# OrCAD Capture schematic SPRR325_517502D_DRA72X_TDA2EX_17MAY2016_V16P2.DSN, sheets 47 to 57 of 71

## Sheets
47 SH58 - ETHERNET PORT0: size B
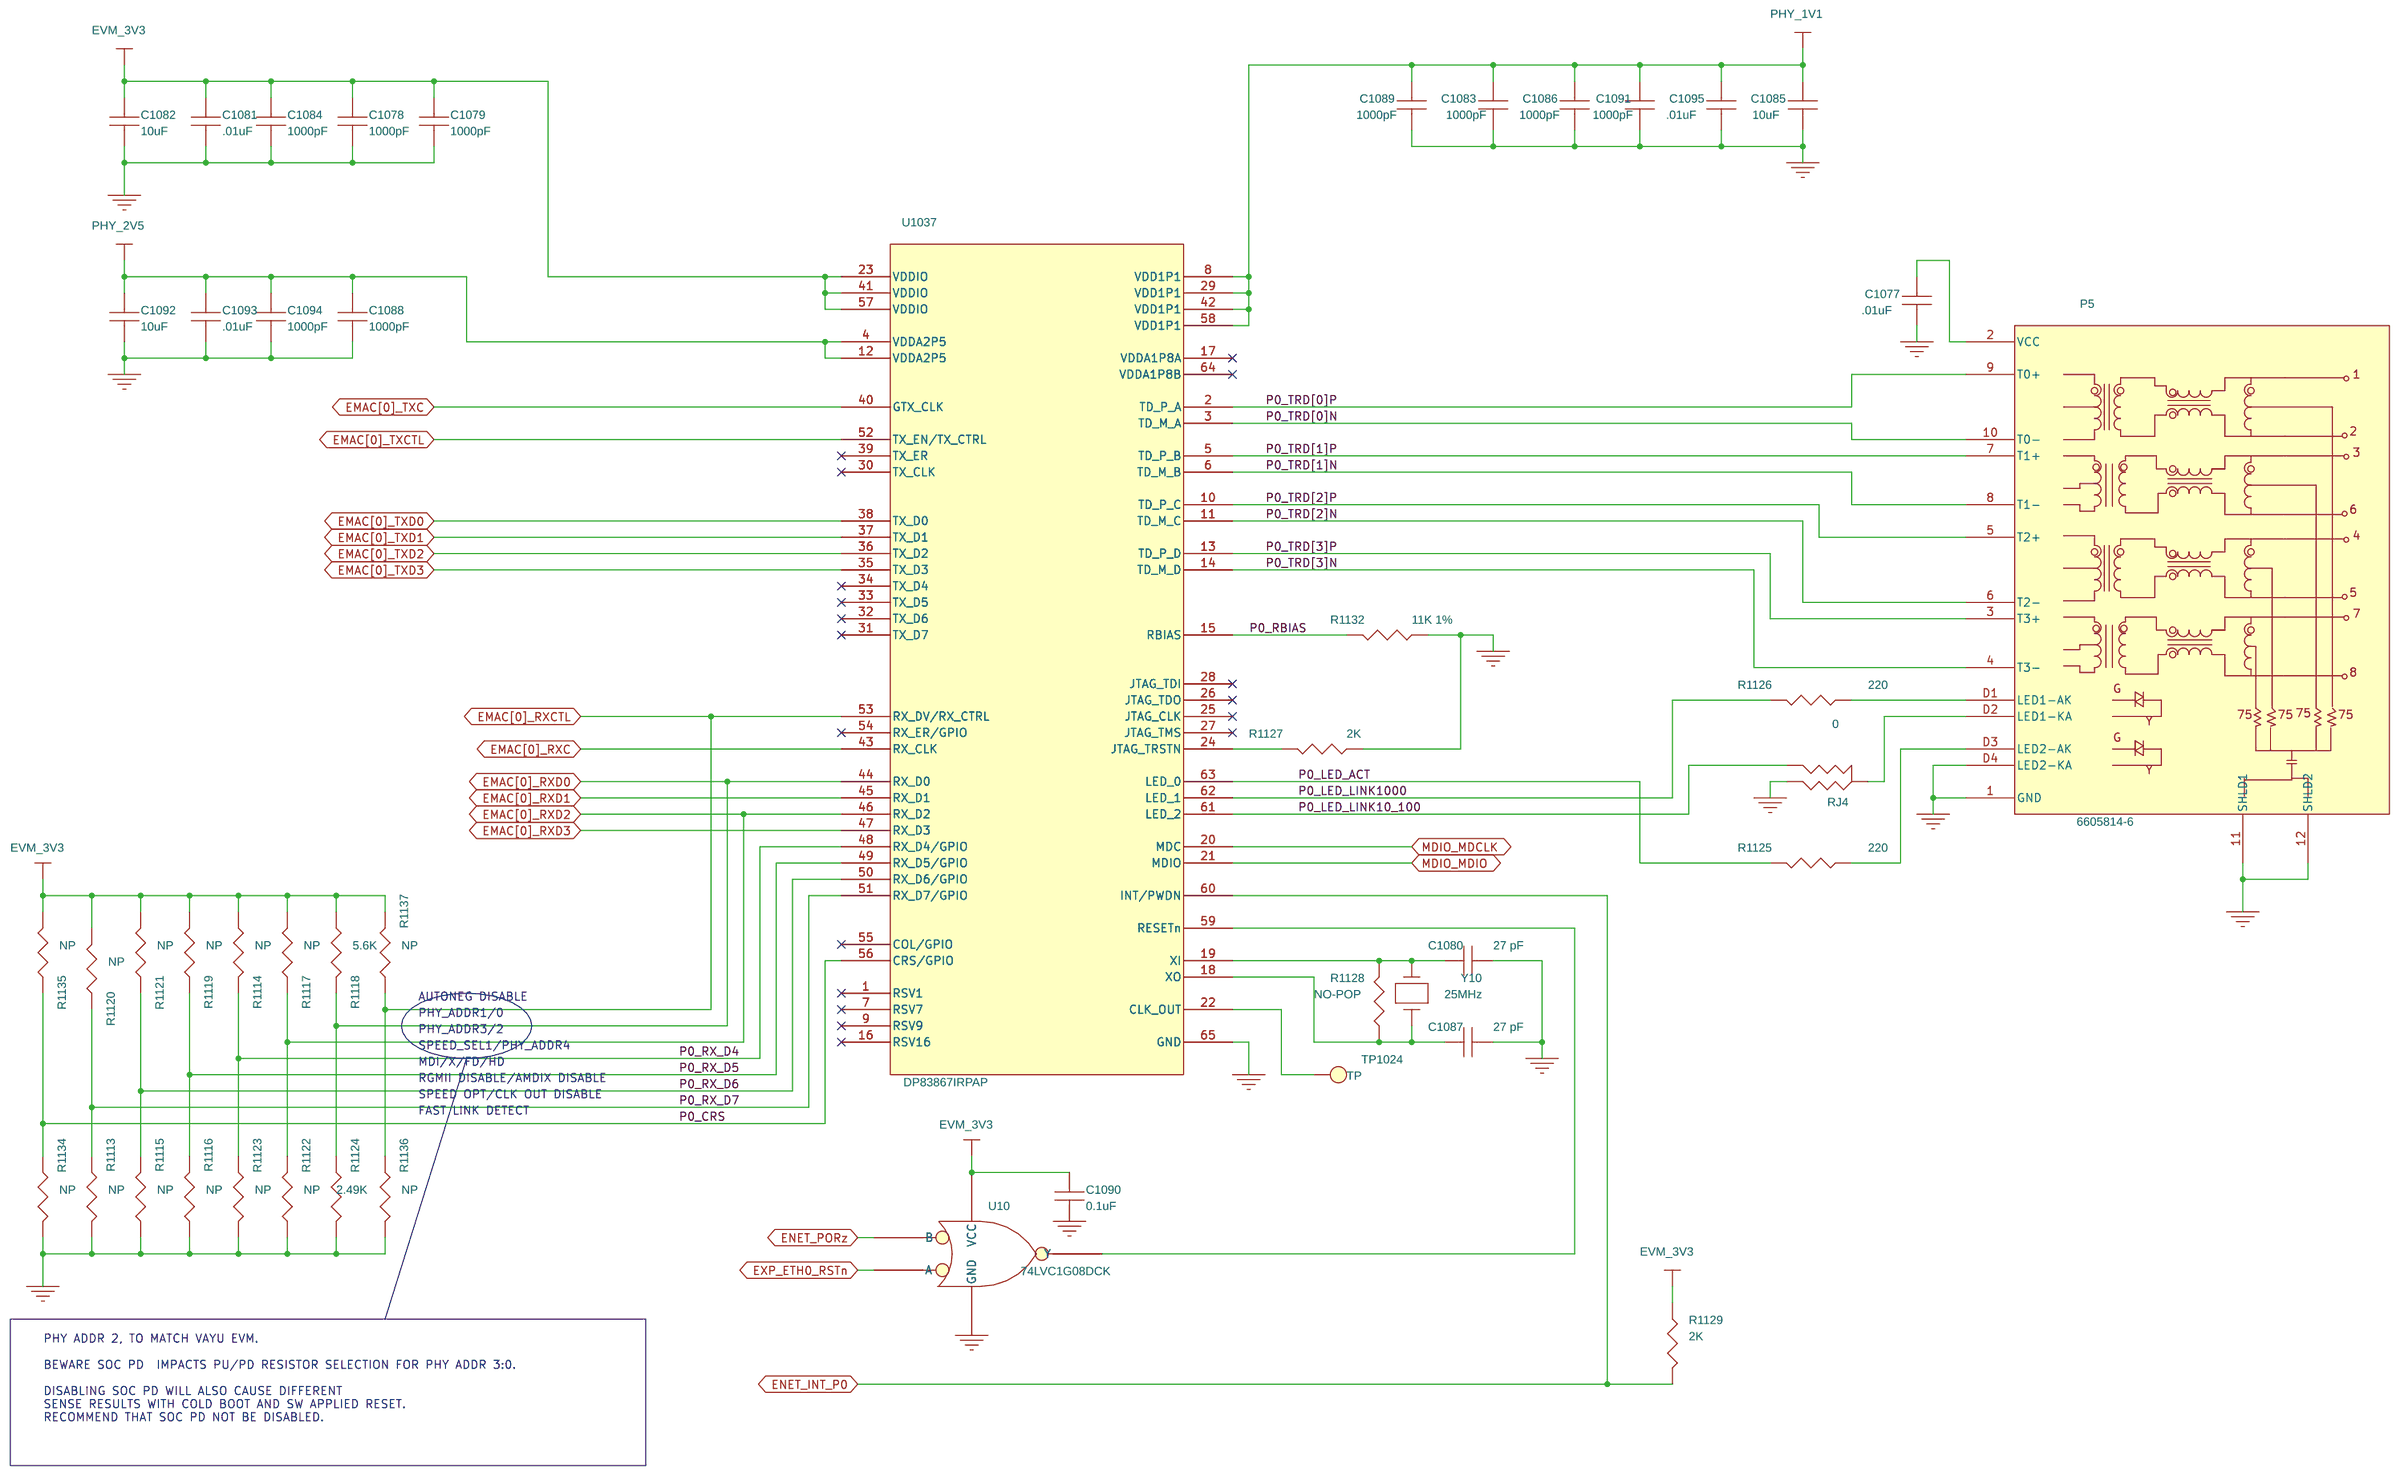
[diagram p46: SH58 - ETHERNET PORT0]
48 SH59 - ETHERNET PORT1: size B
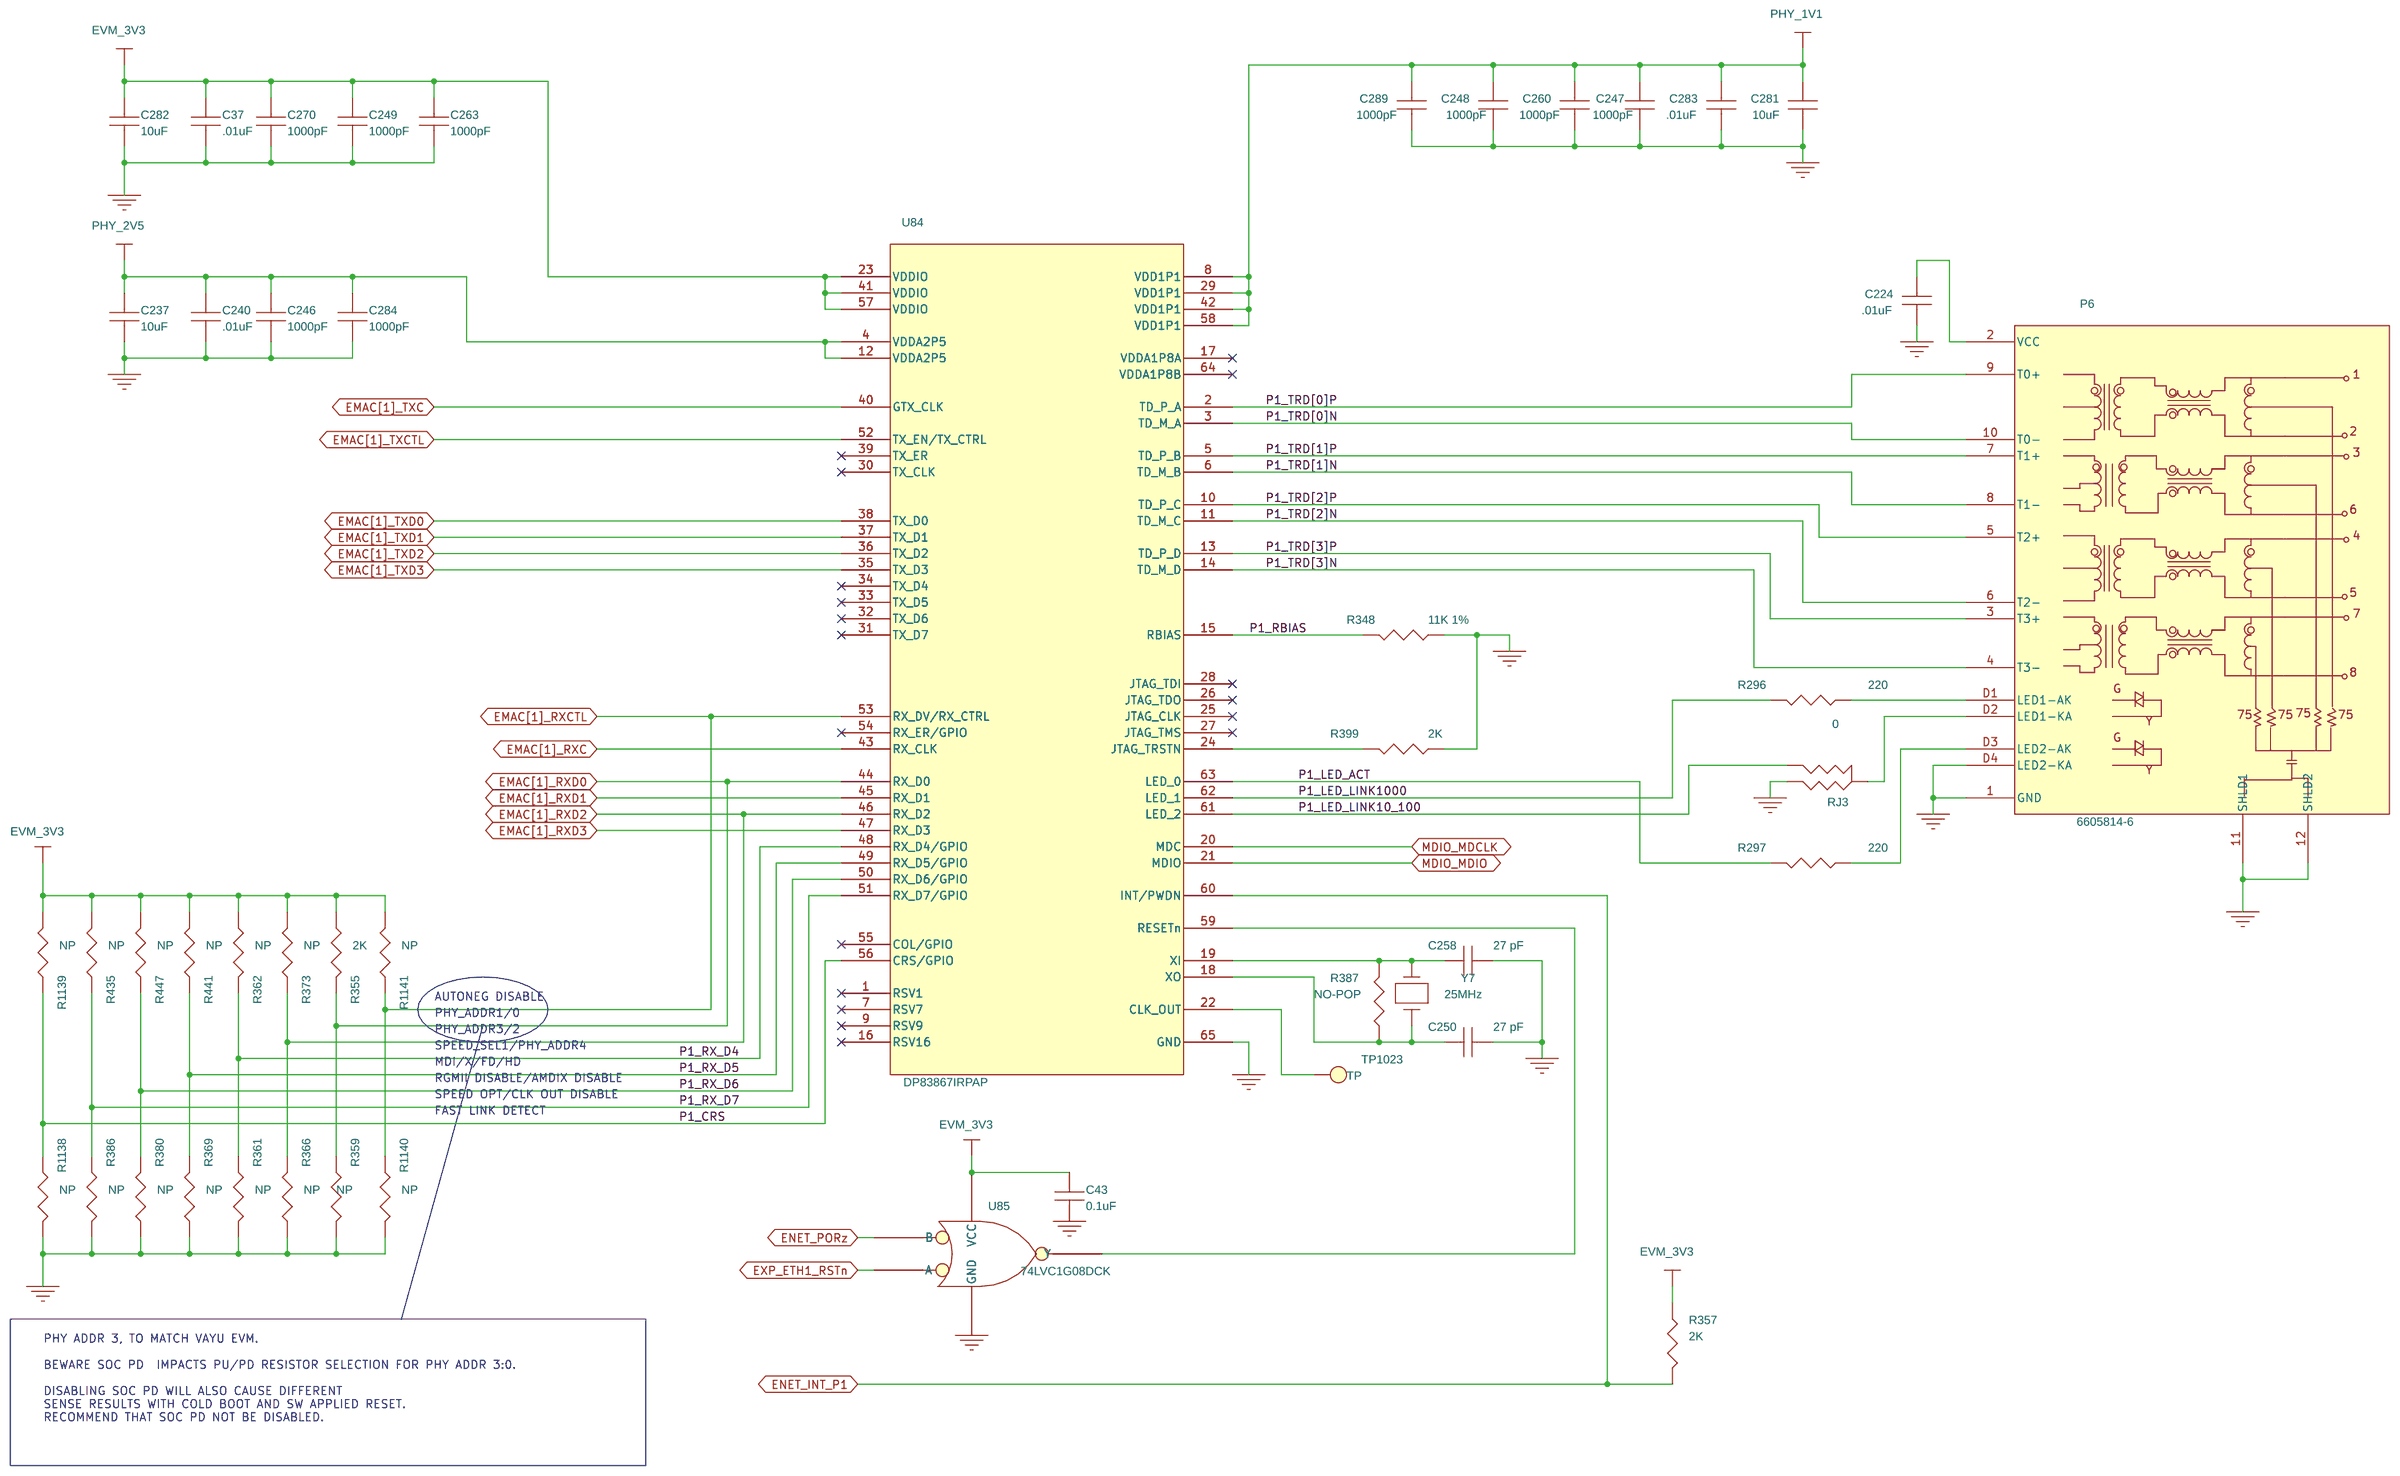
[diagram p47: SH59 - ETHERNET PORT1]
49 SH60 - APPLICATION IF CONN1: size B; rev: C
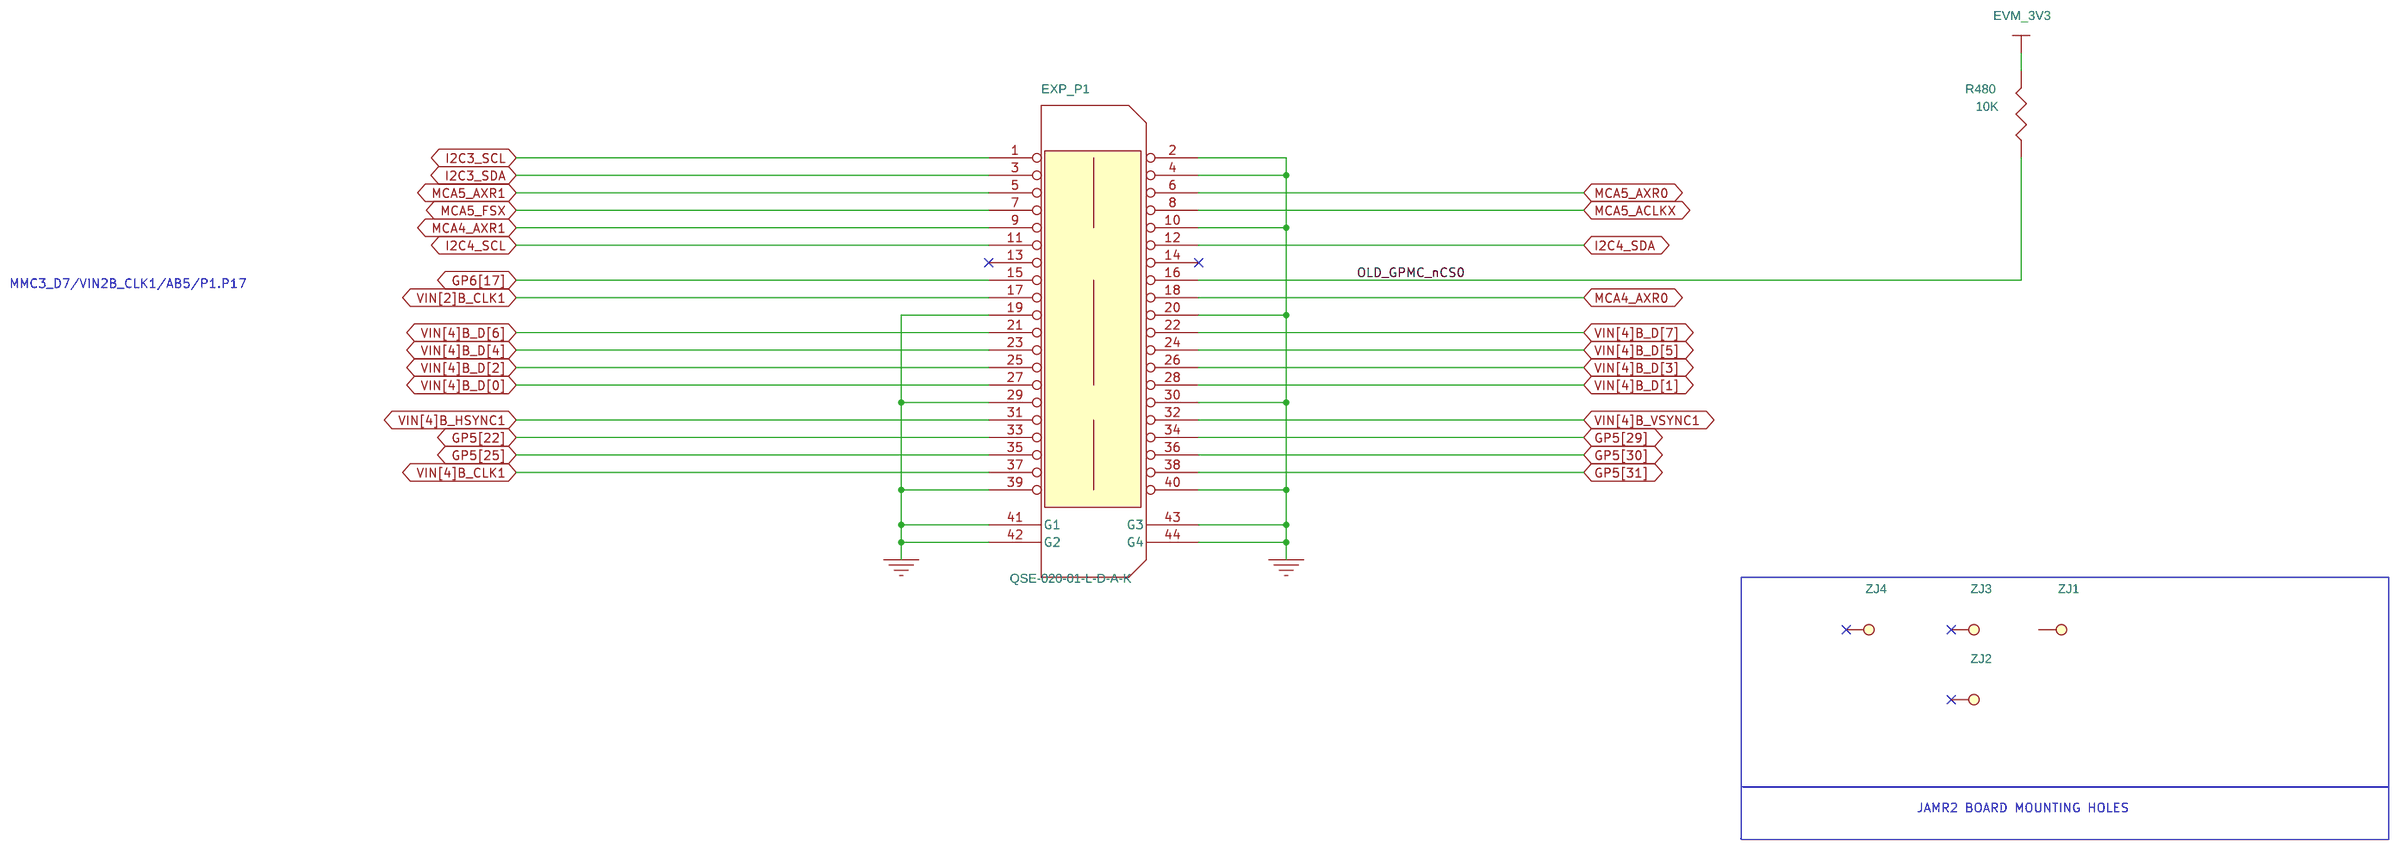
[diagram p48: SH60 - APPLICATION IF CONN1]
50 SH61 - APPLICATION IF  CONN2: size B; rev: C
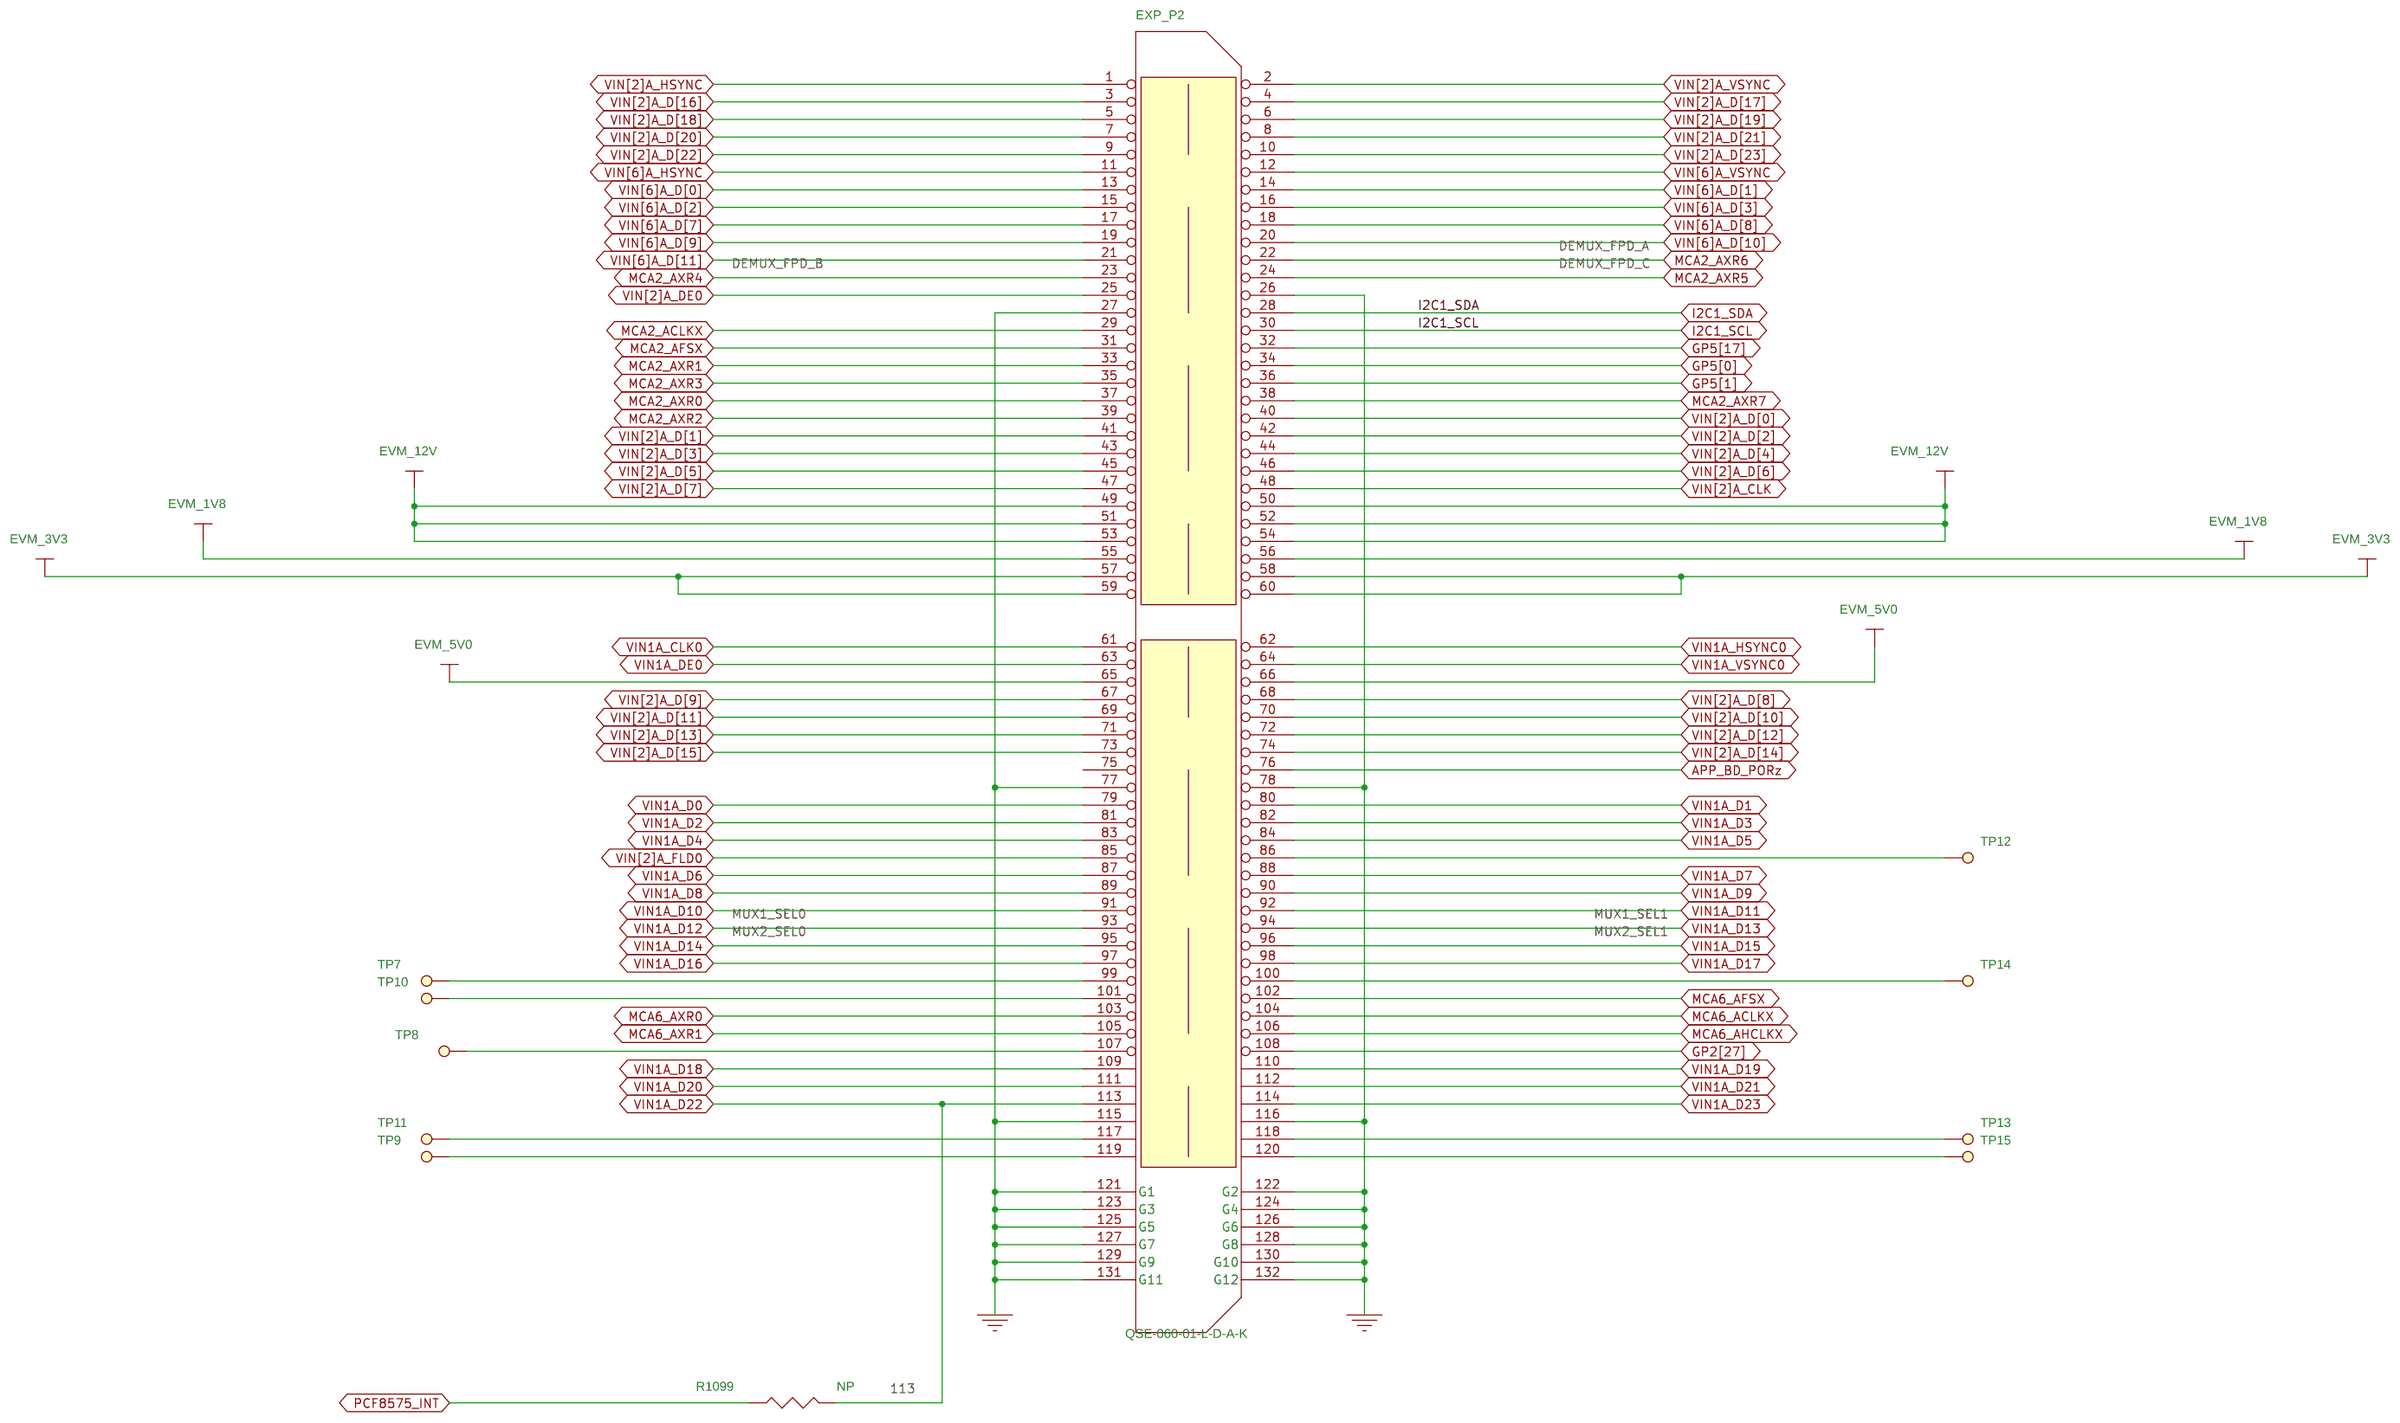
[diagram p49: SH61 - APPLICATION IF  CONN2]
51 SH62 - APPLICATION IF  CONN3: size B; rev: C
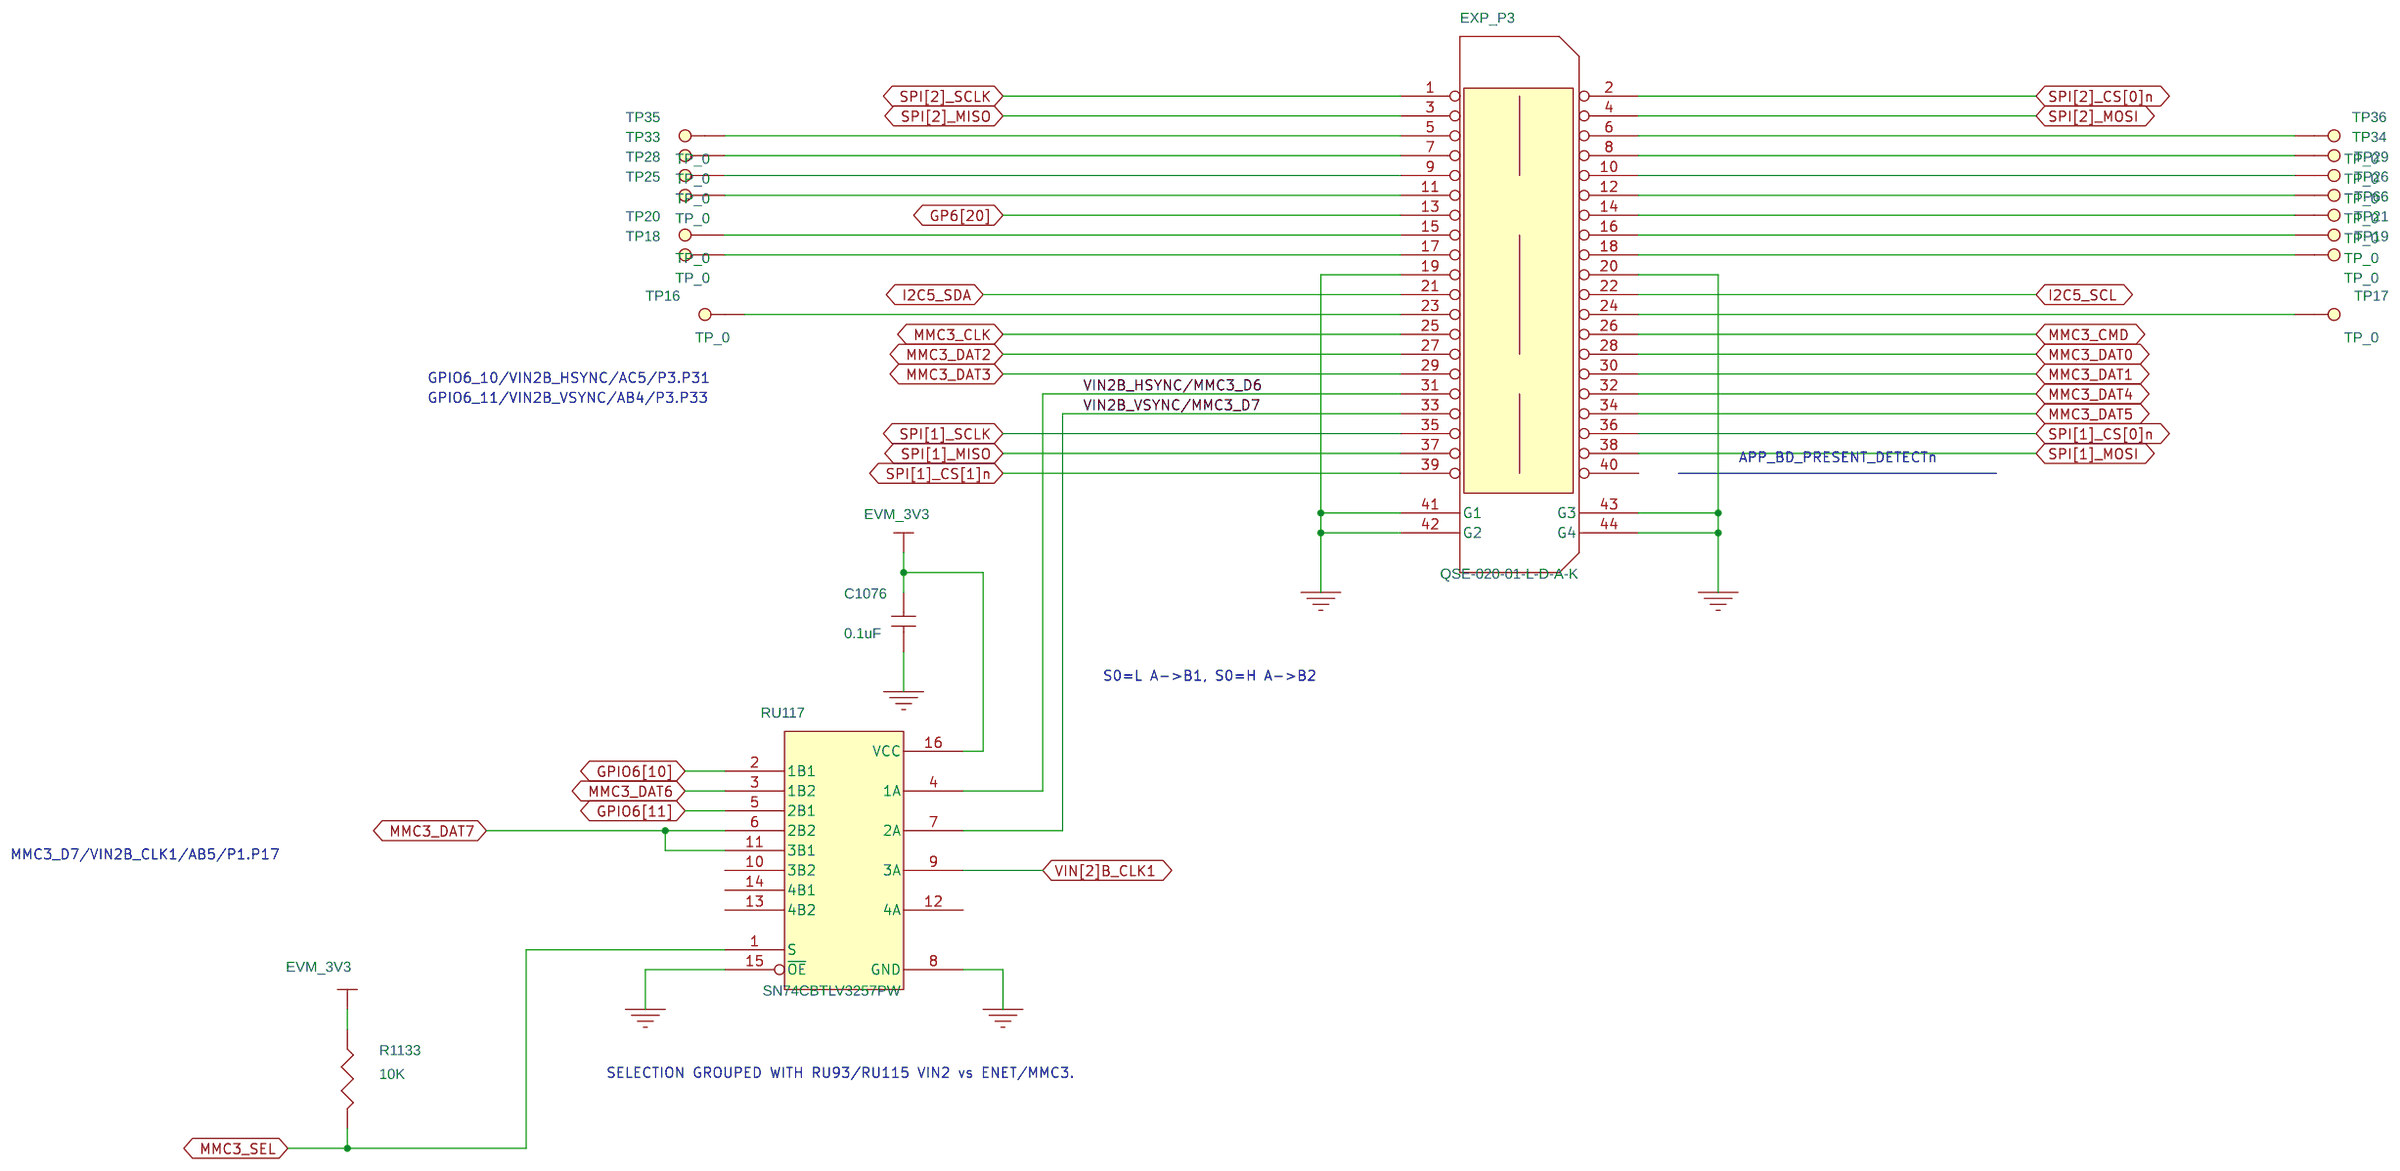
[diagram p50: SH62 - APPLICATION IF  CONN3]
52 SH63 - RESET: size B; rev: A
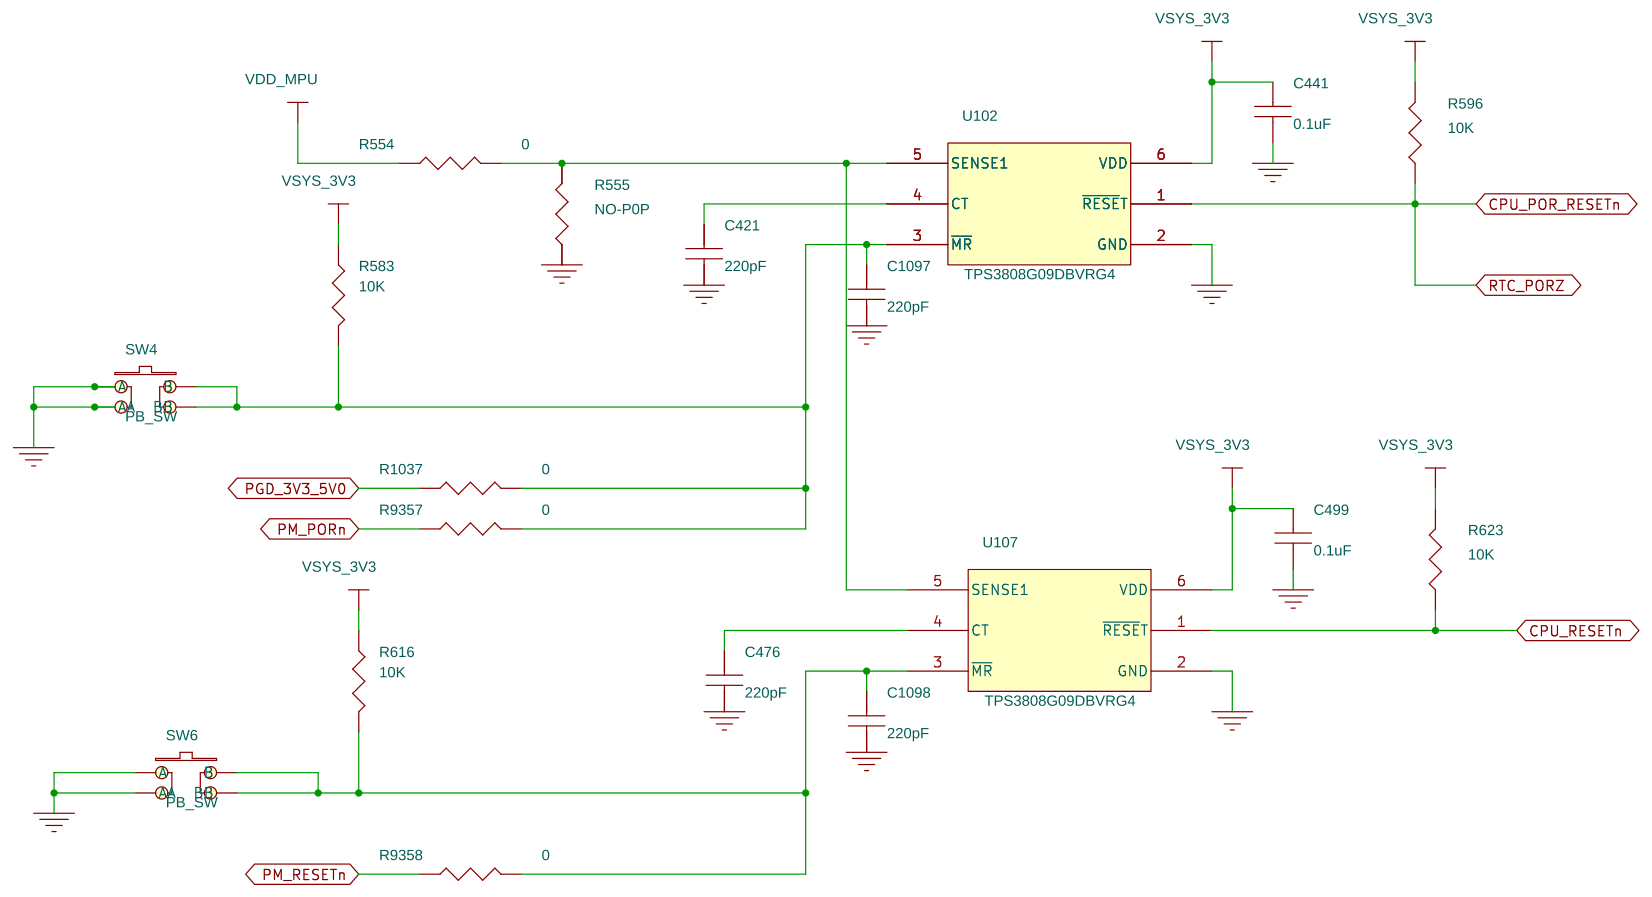
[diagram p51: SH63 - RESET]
53 SH64 - POWER INPUT: size B; rev: C
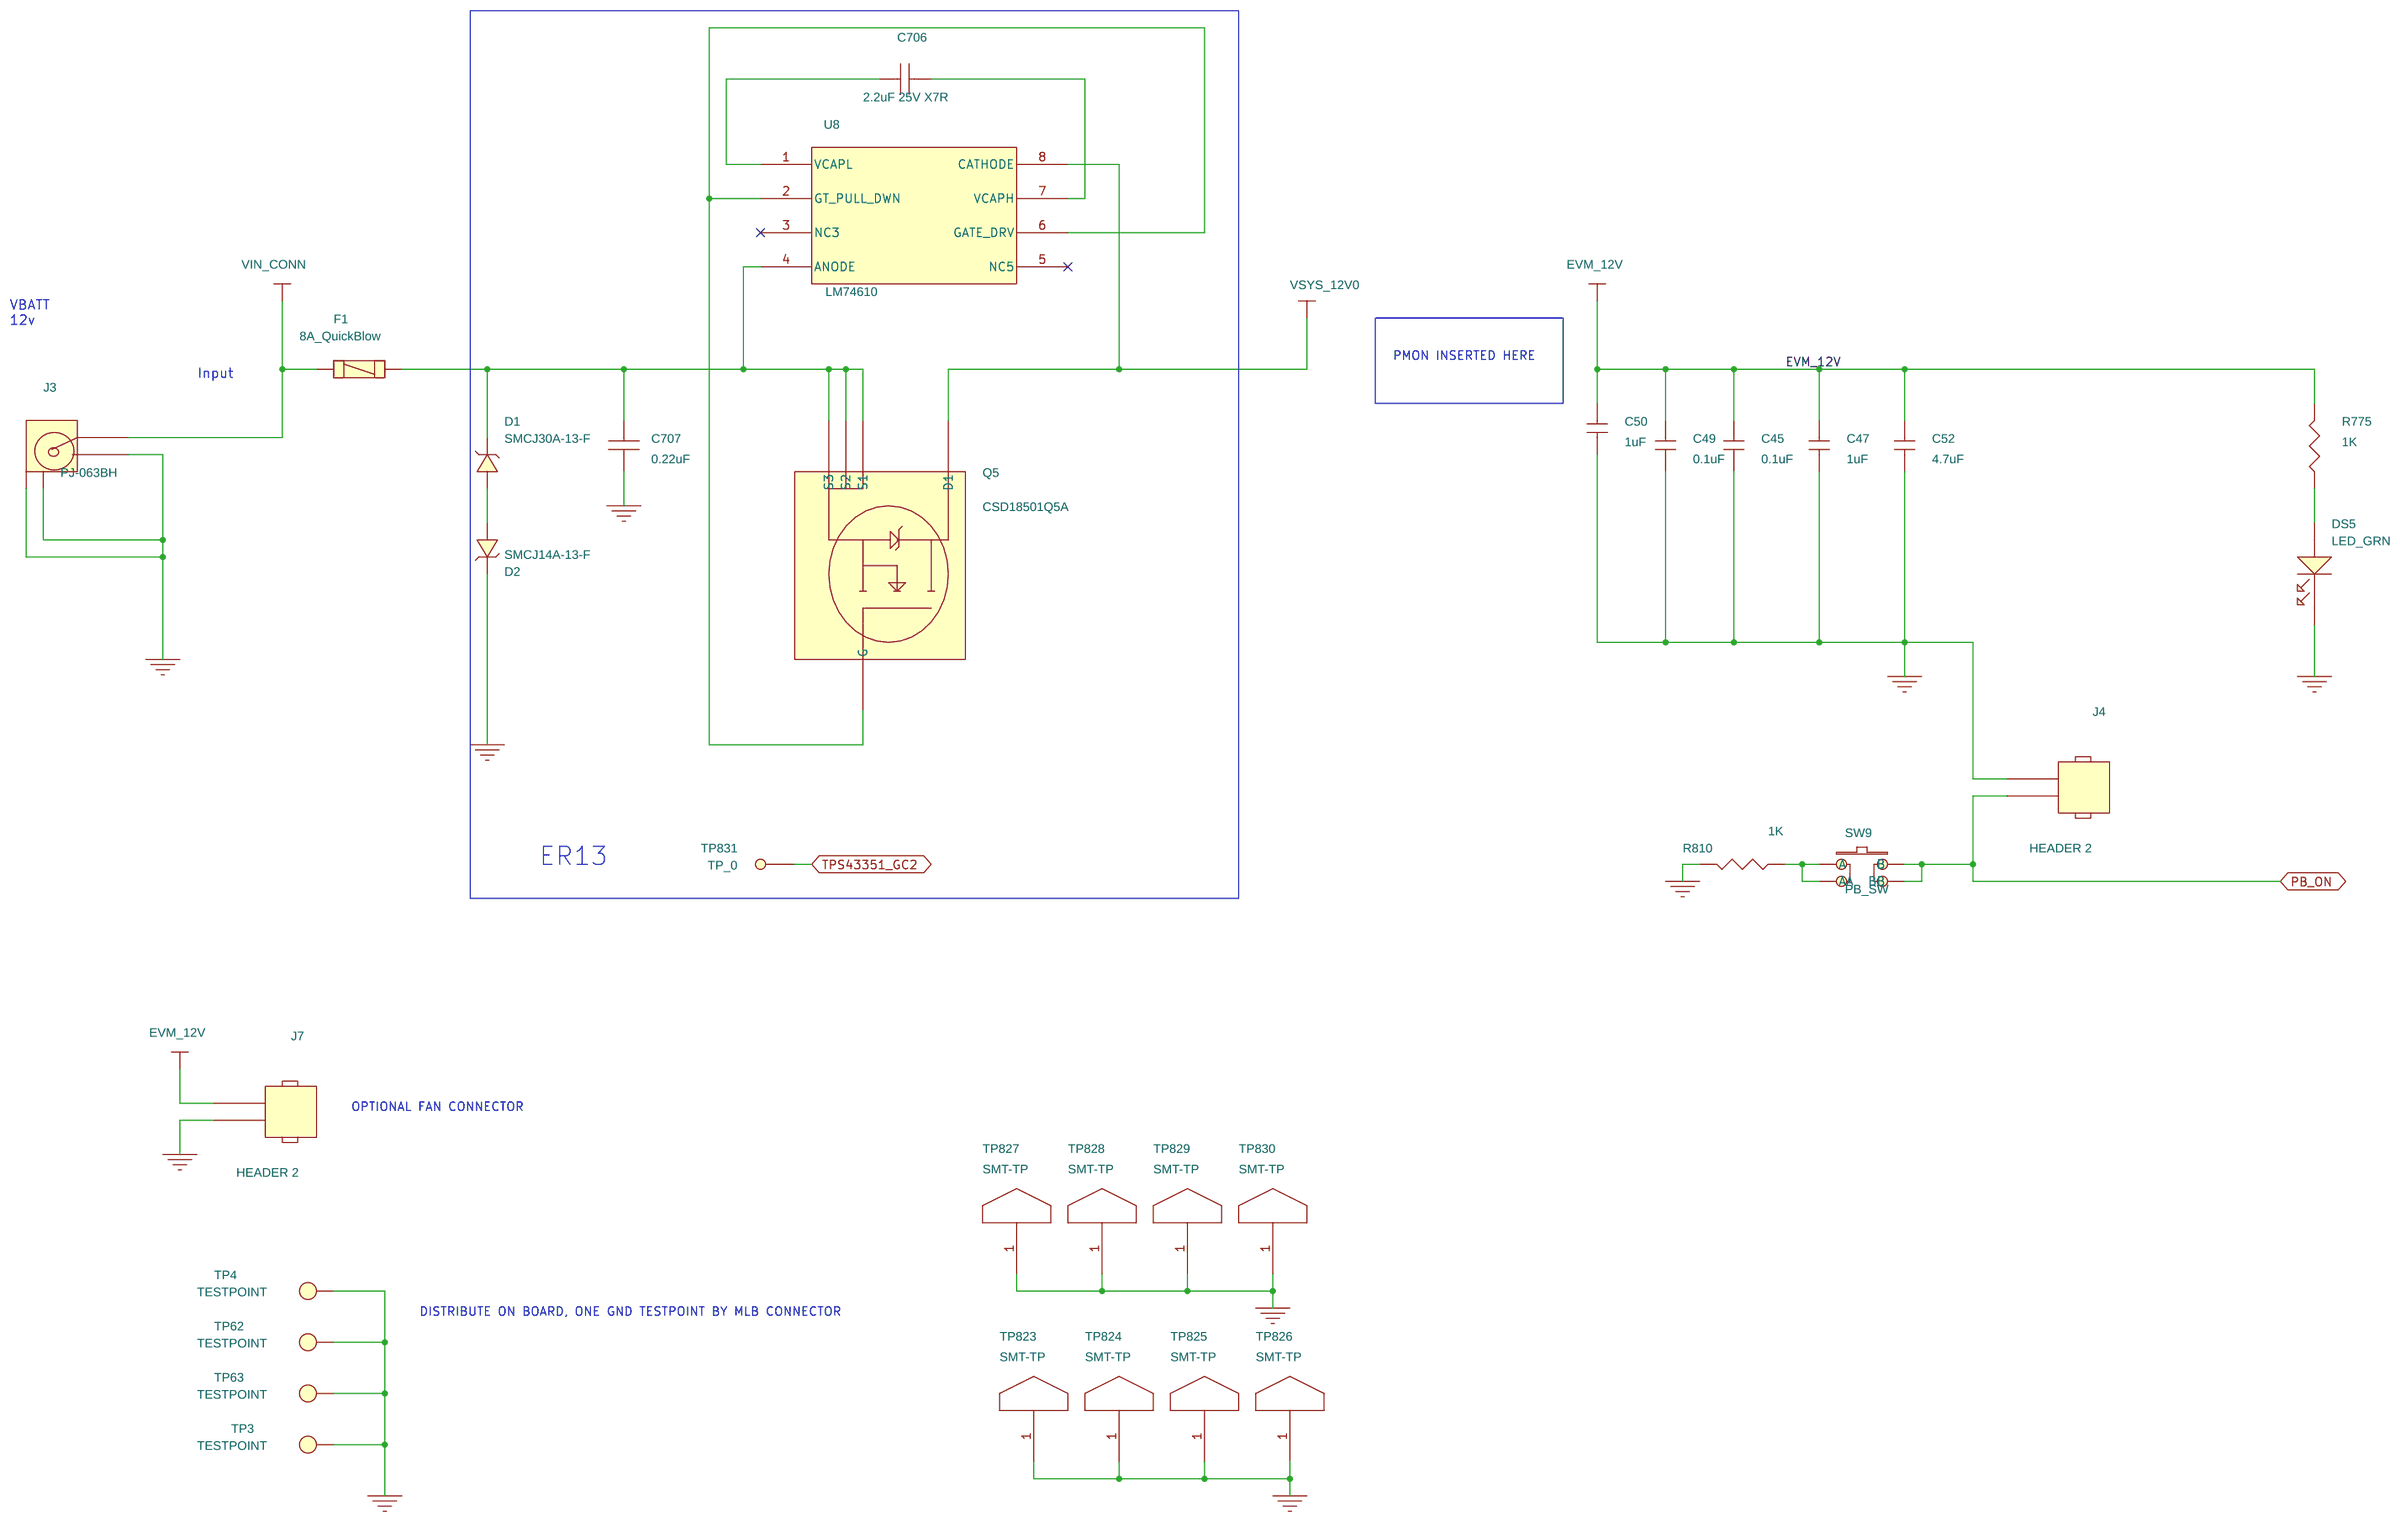
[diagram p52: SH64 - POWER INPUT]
54 SH65 - POWER TPS443351DAP: size B; rev: A
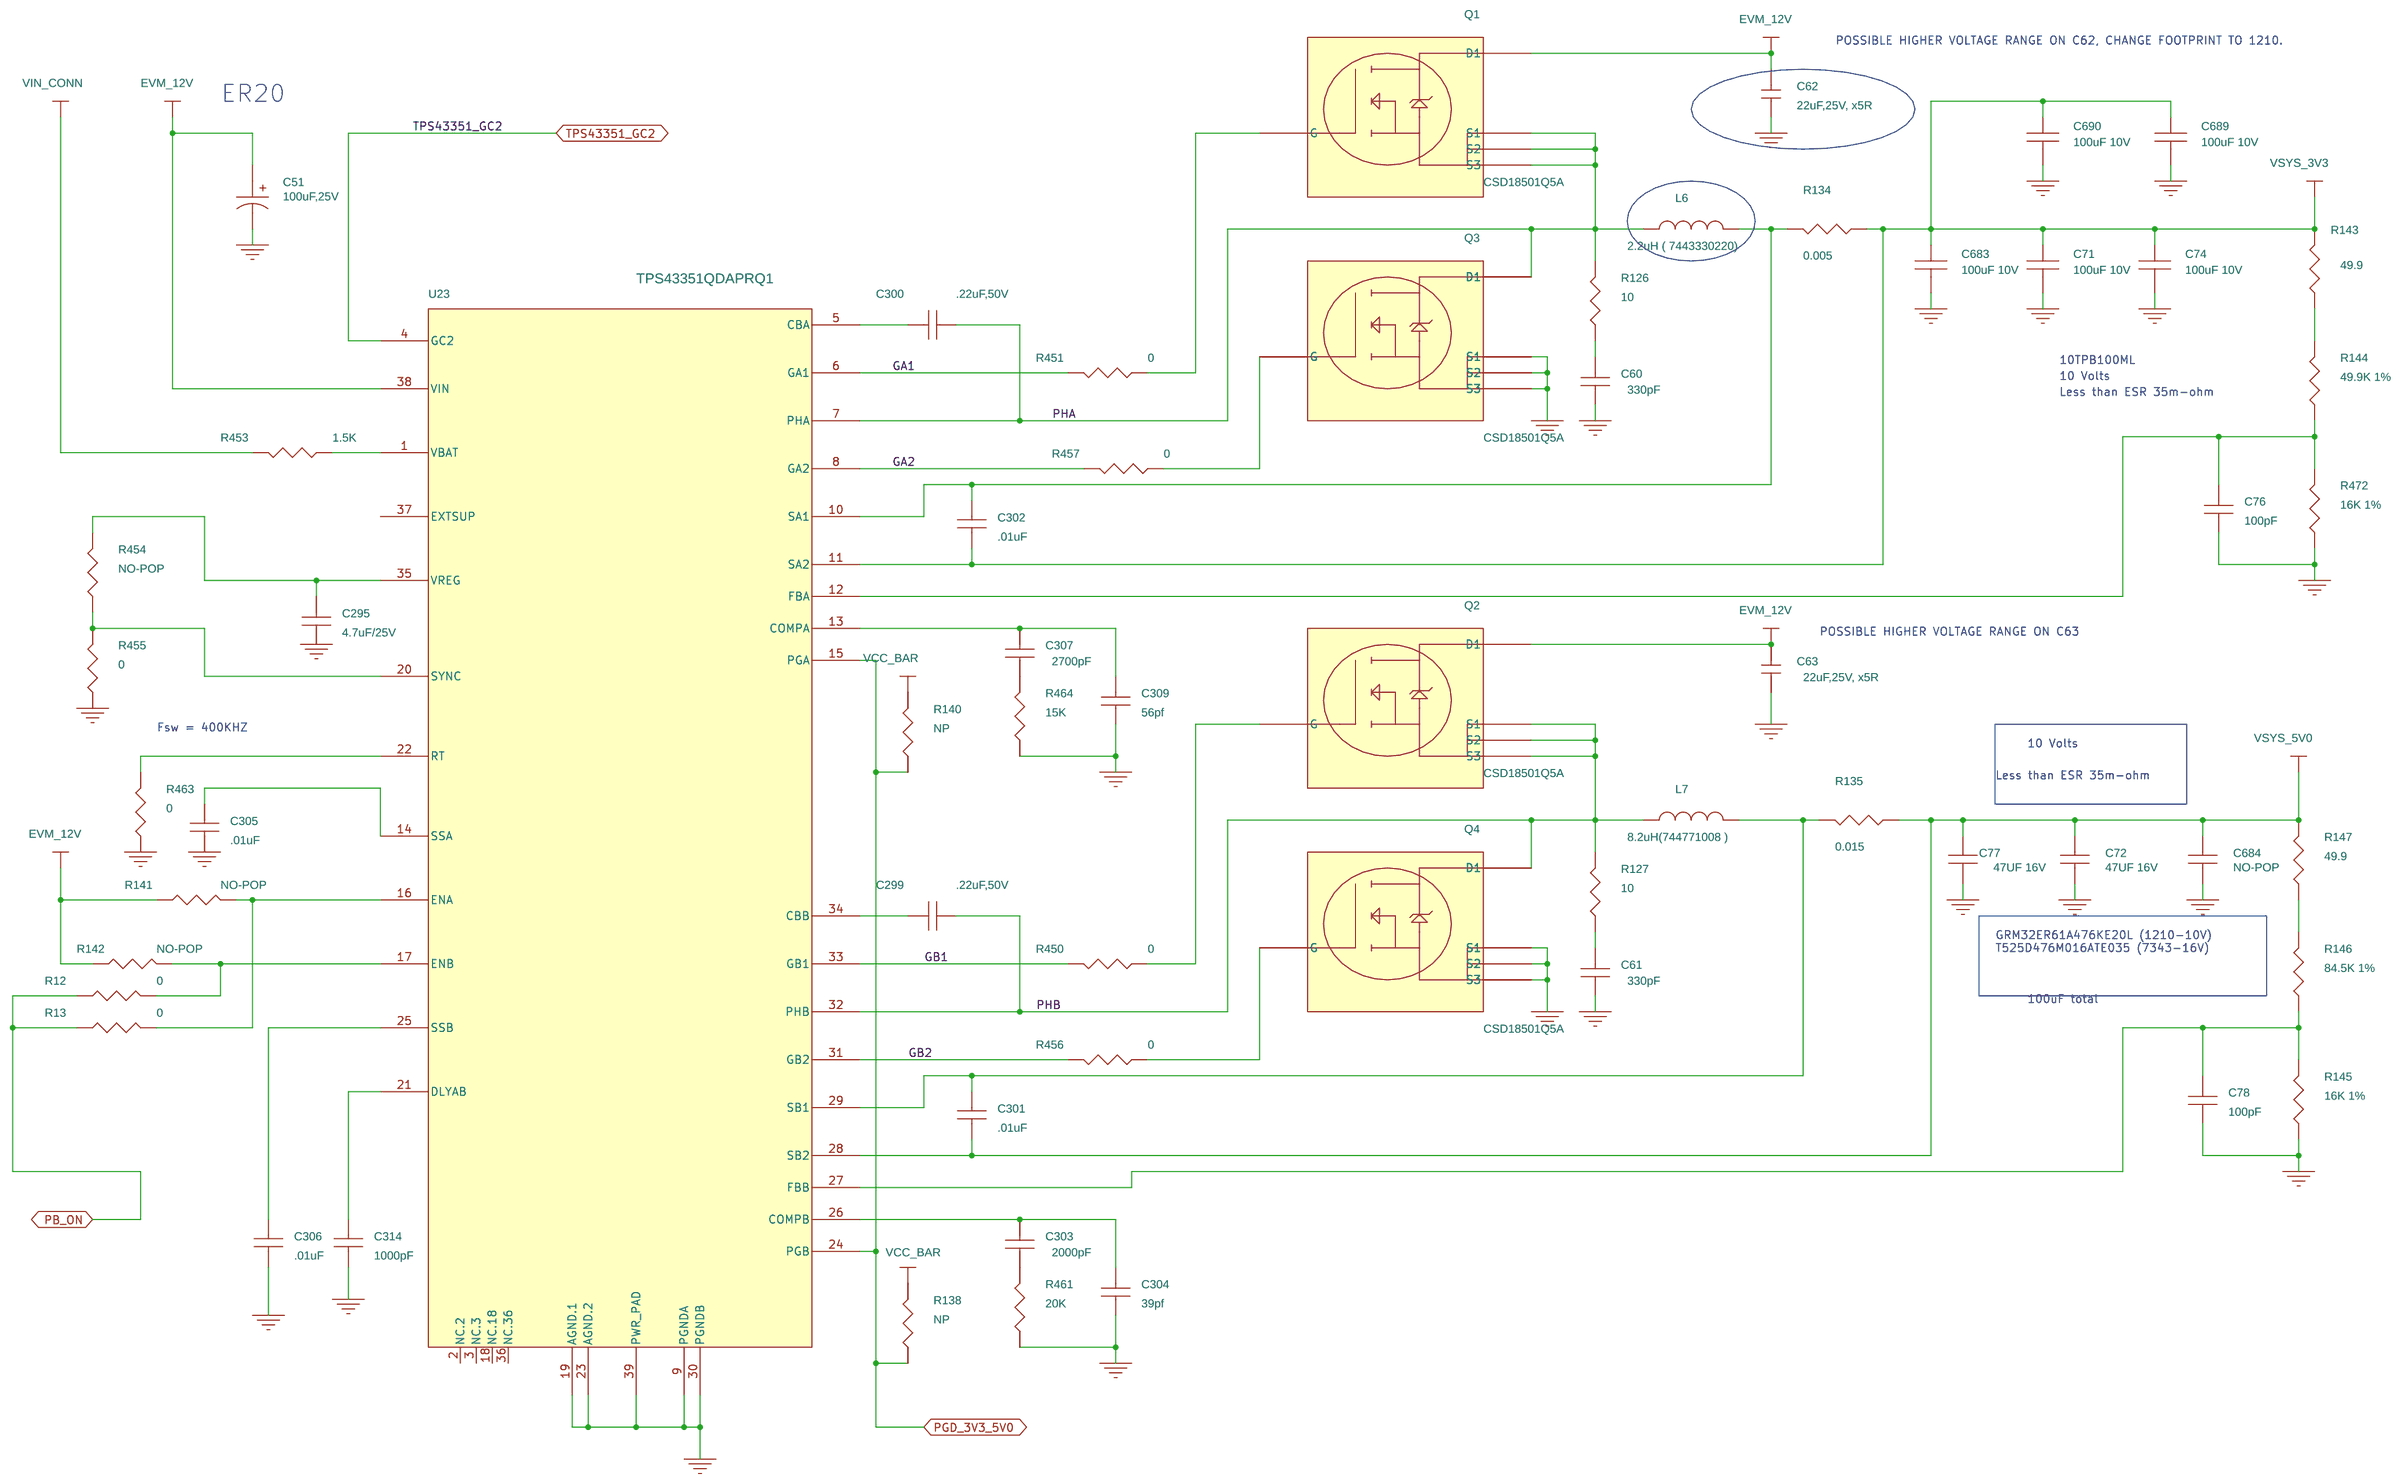
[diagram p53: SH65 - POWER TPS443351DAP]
55 SH66 - MISC POWER SWITCHES: size B; rev: C
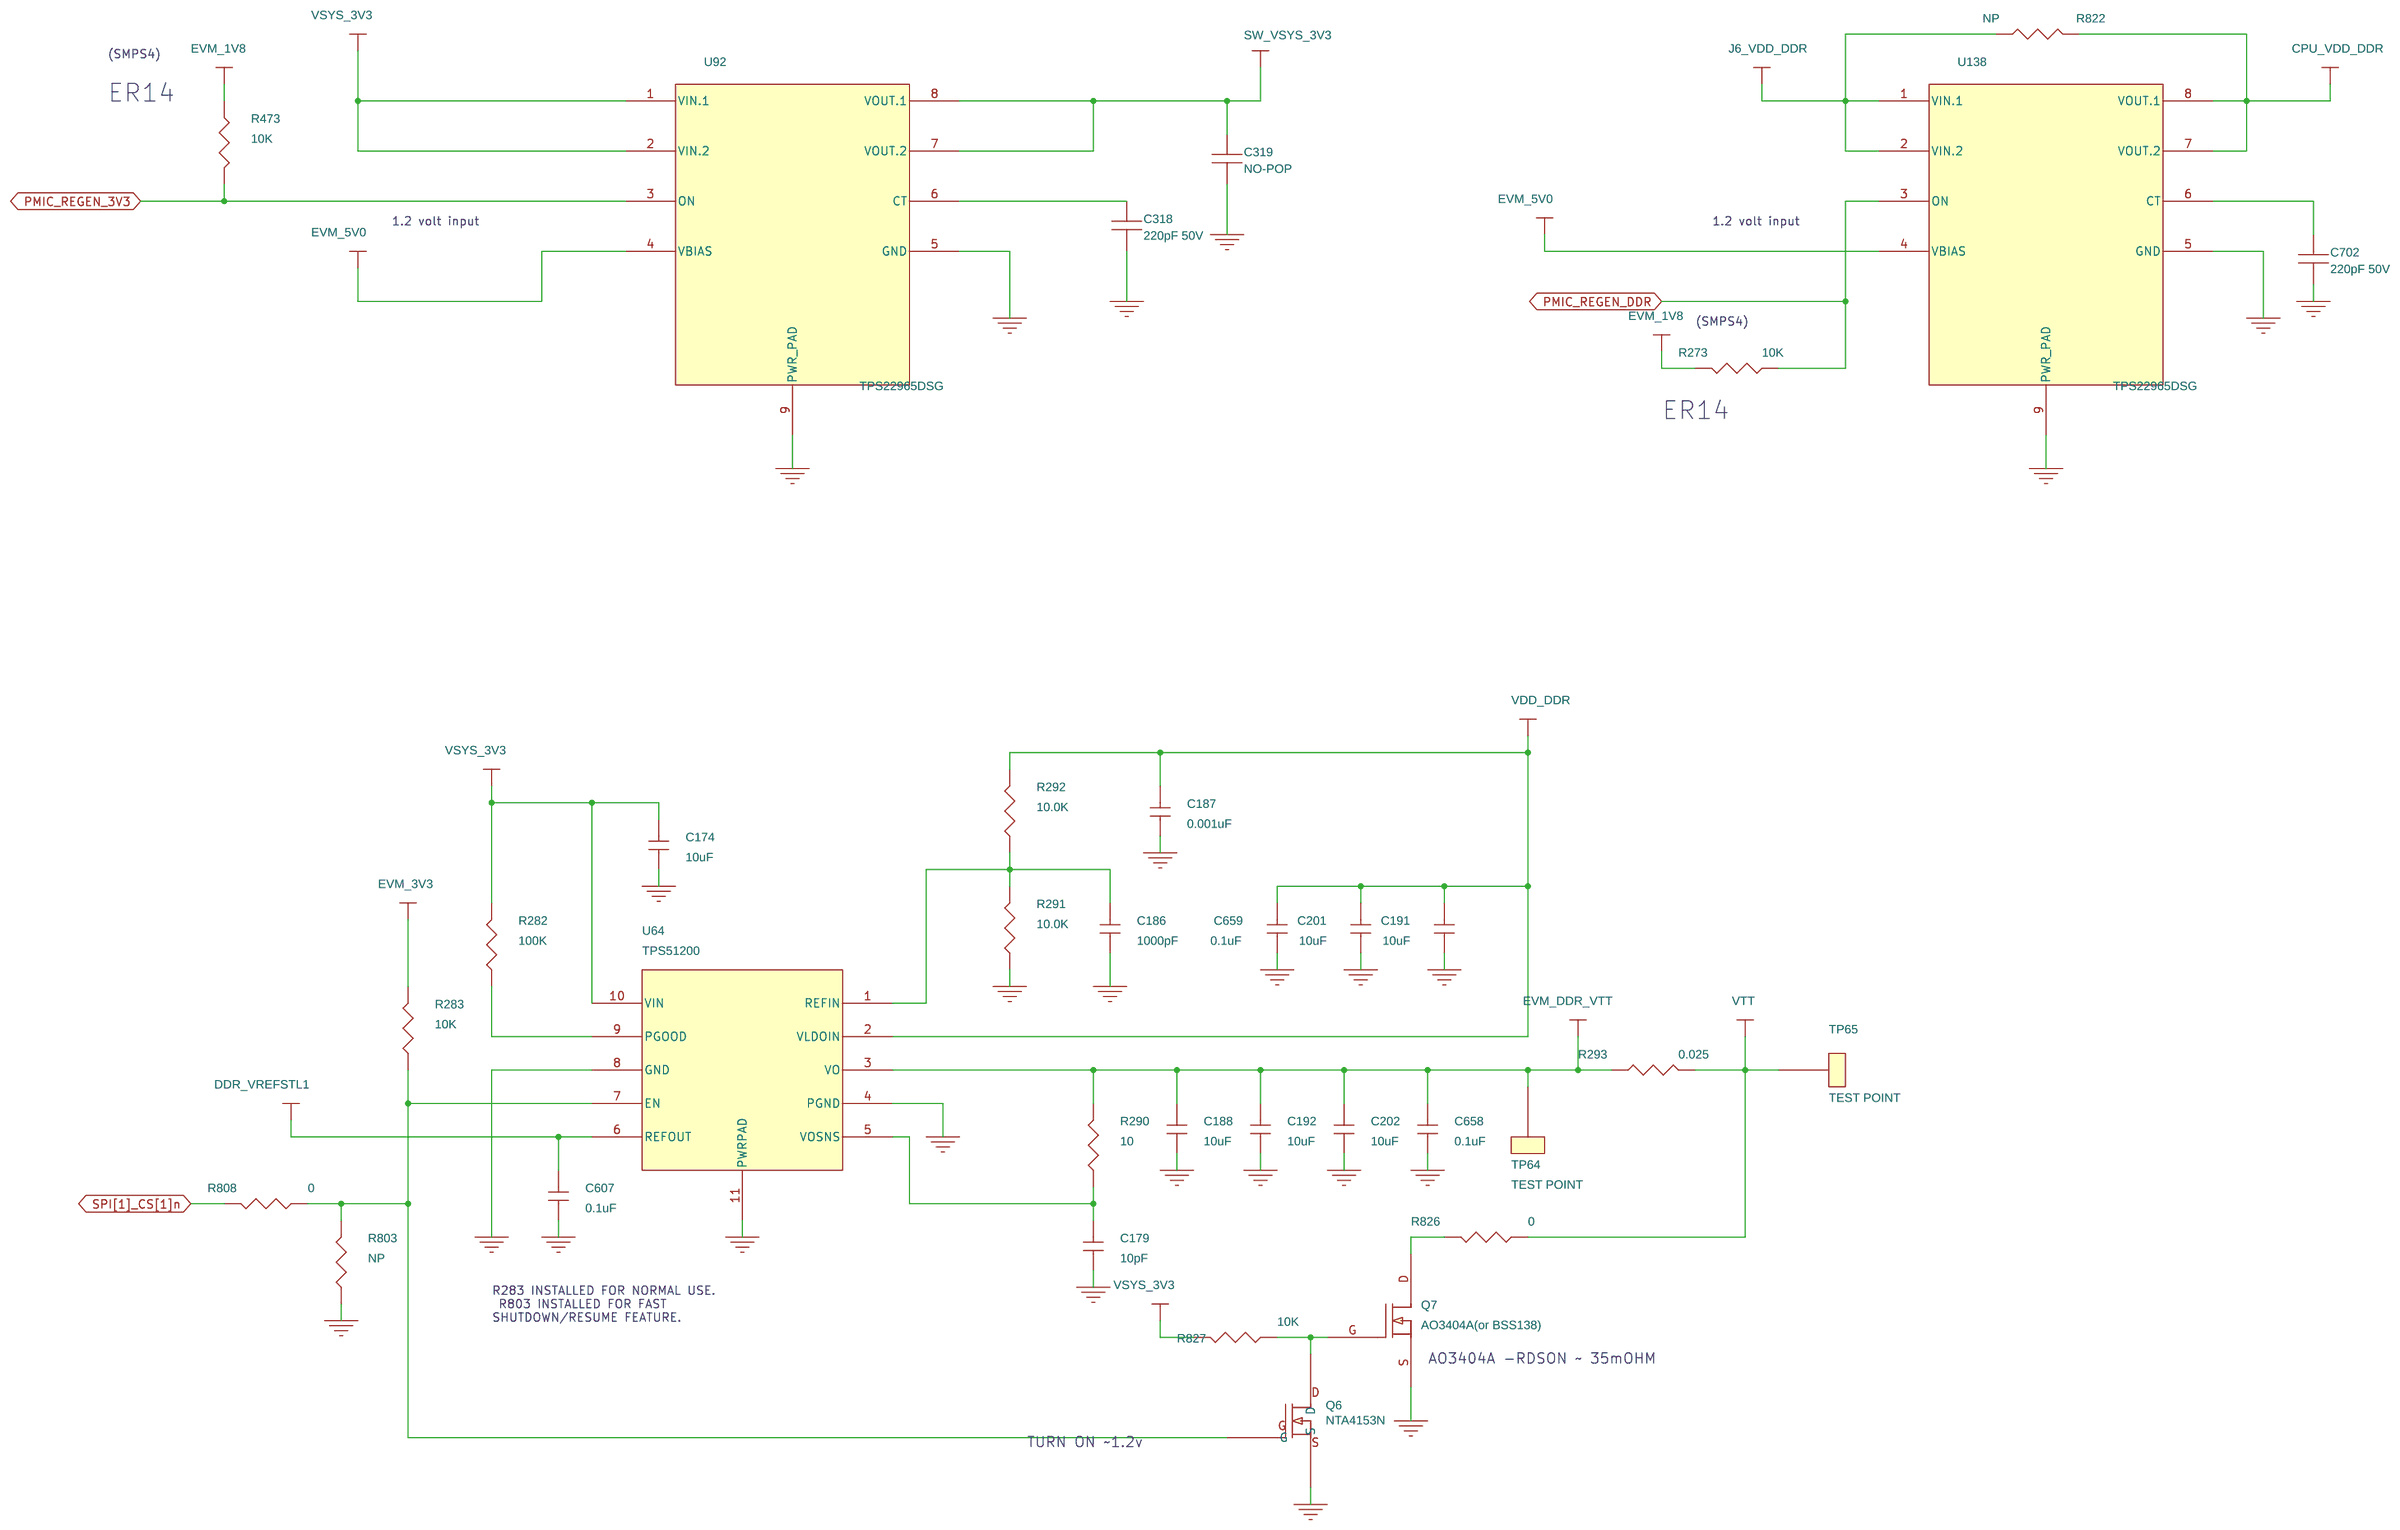
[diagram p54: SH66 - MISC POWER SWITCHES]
56 SH67 - PMIC: size B
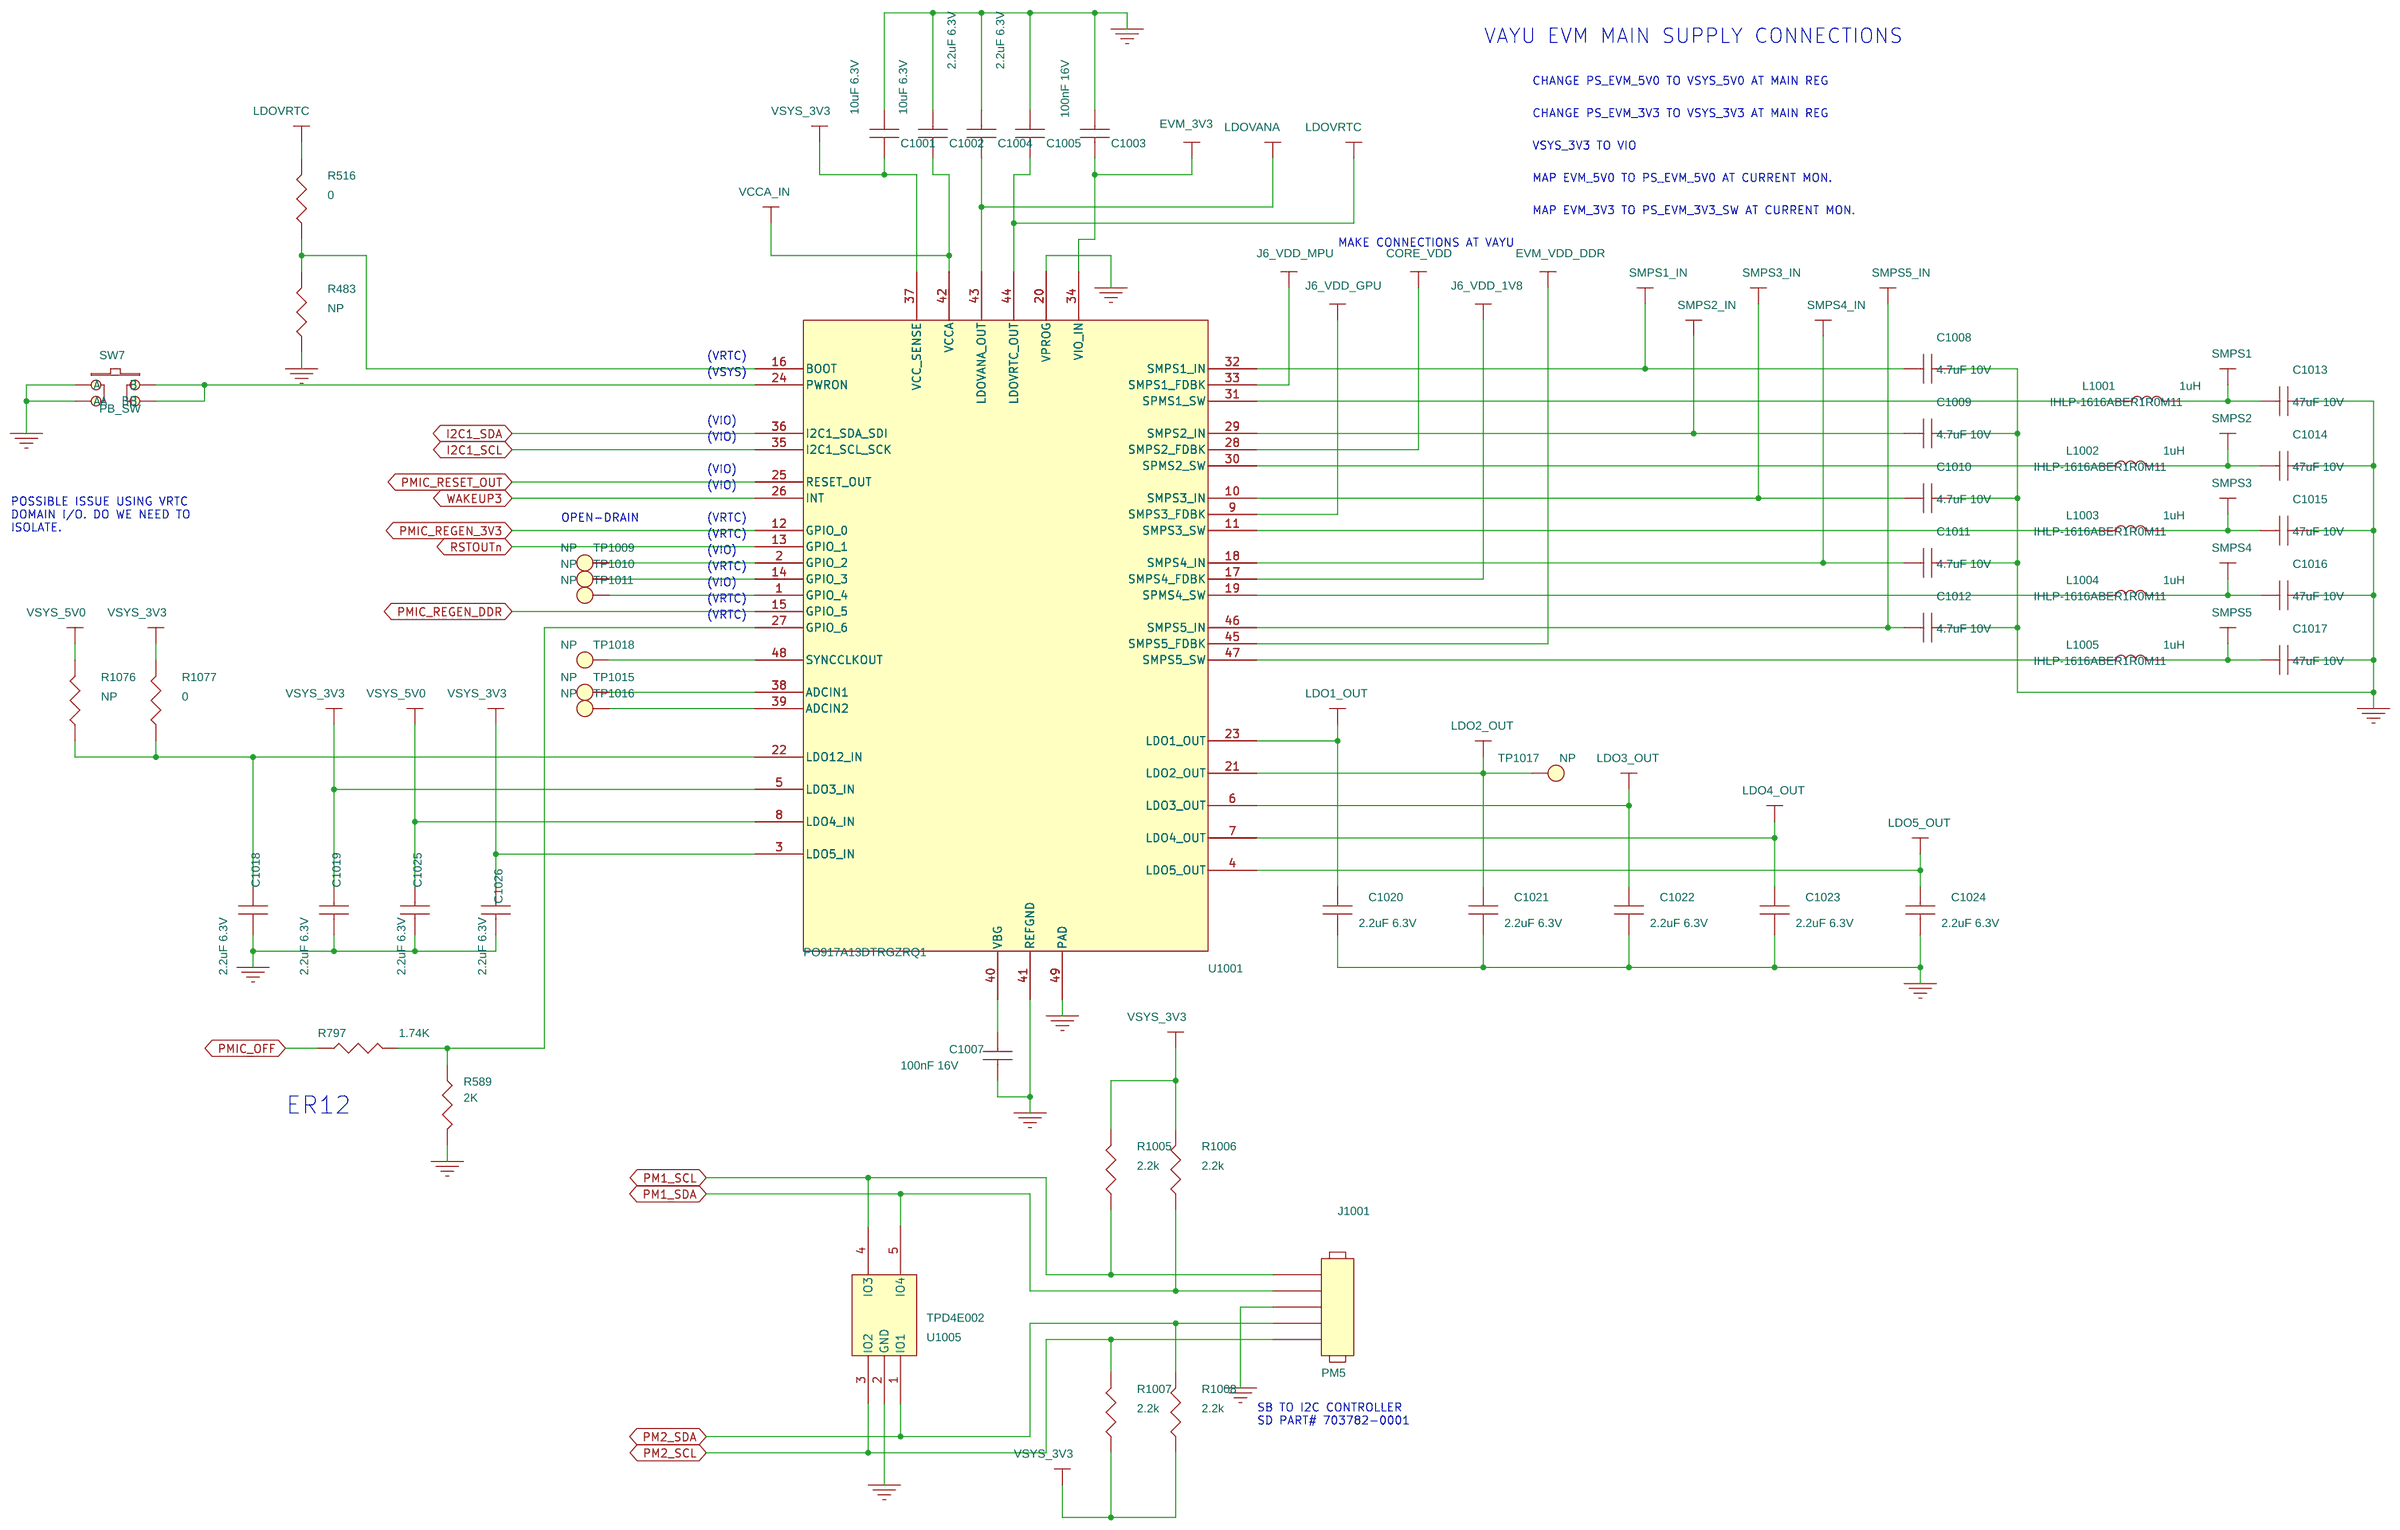
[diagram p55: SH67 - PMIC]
57 SH68 - POWER MONITOR 1: size B; rev: C
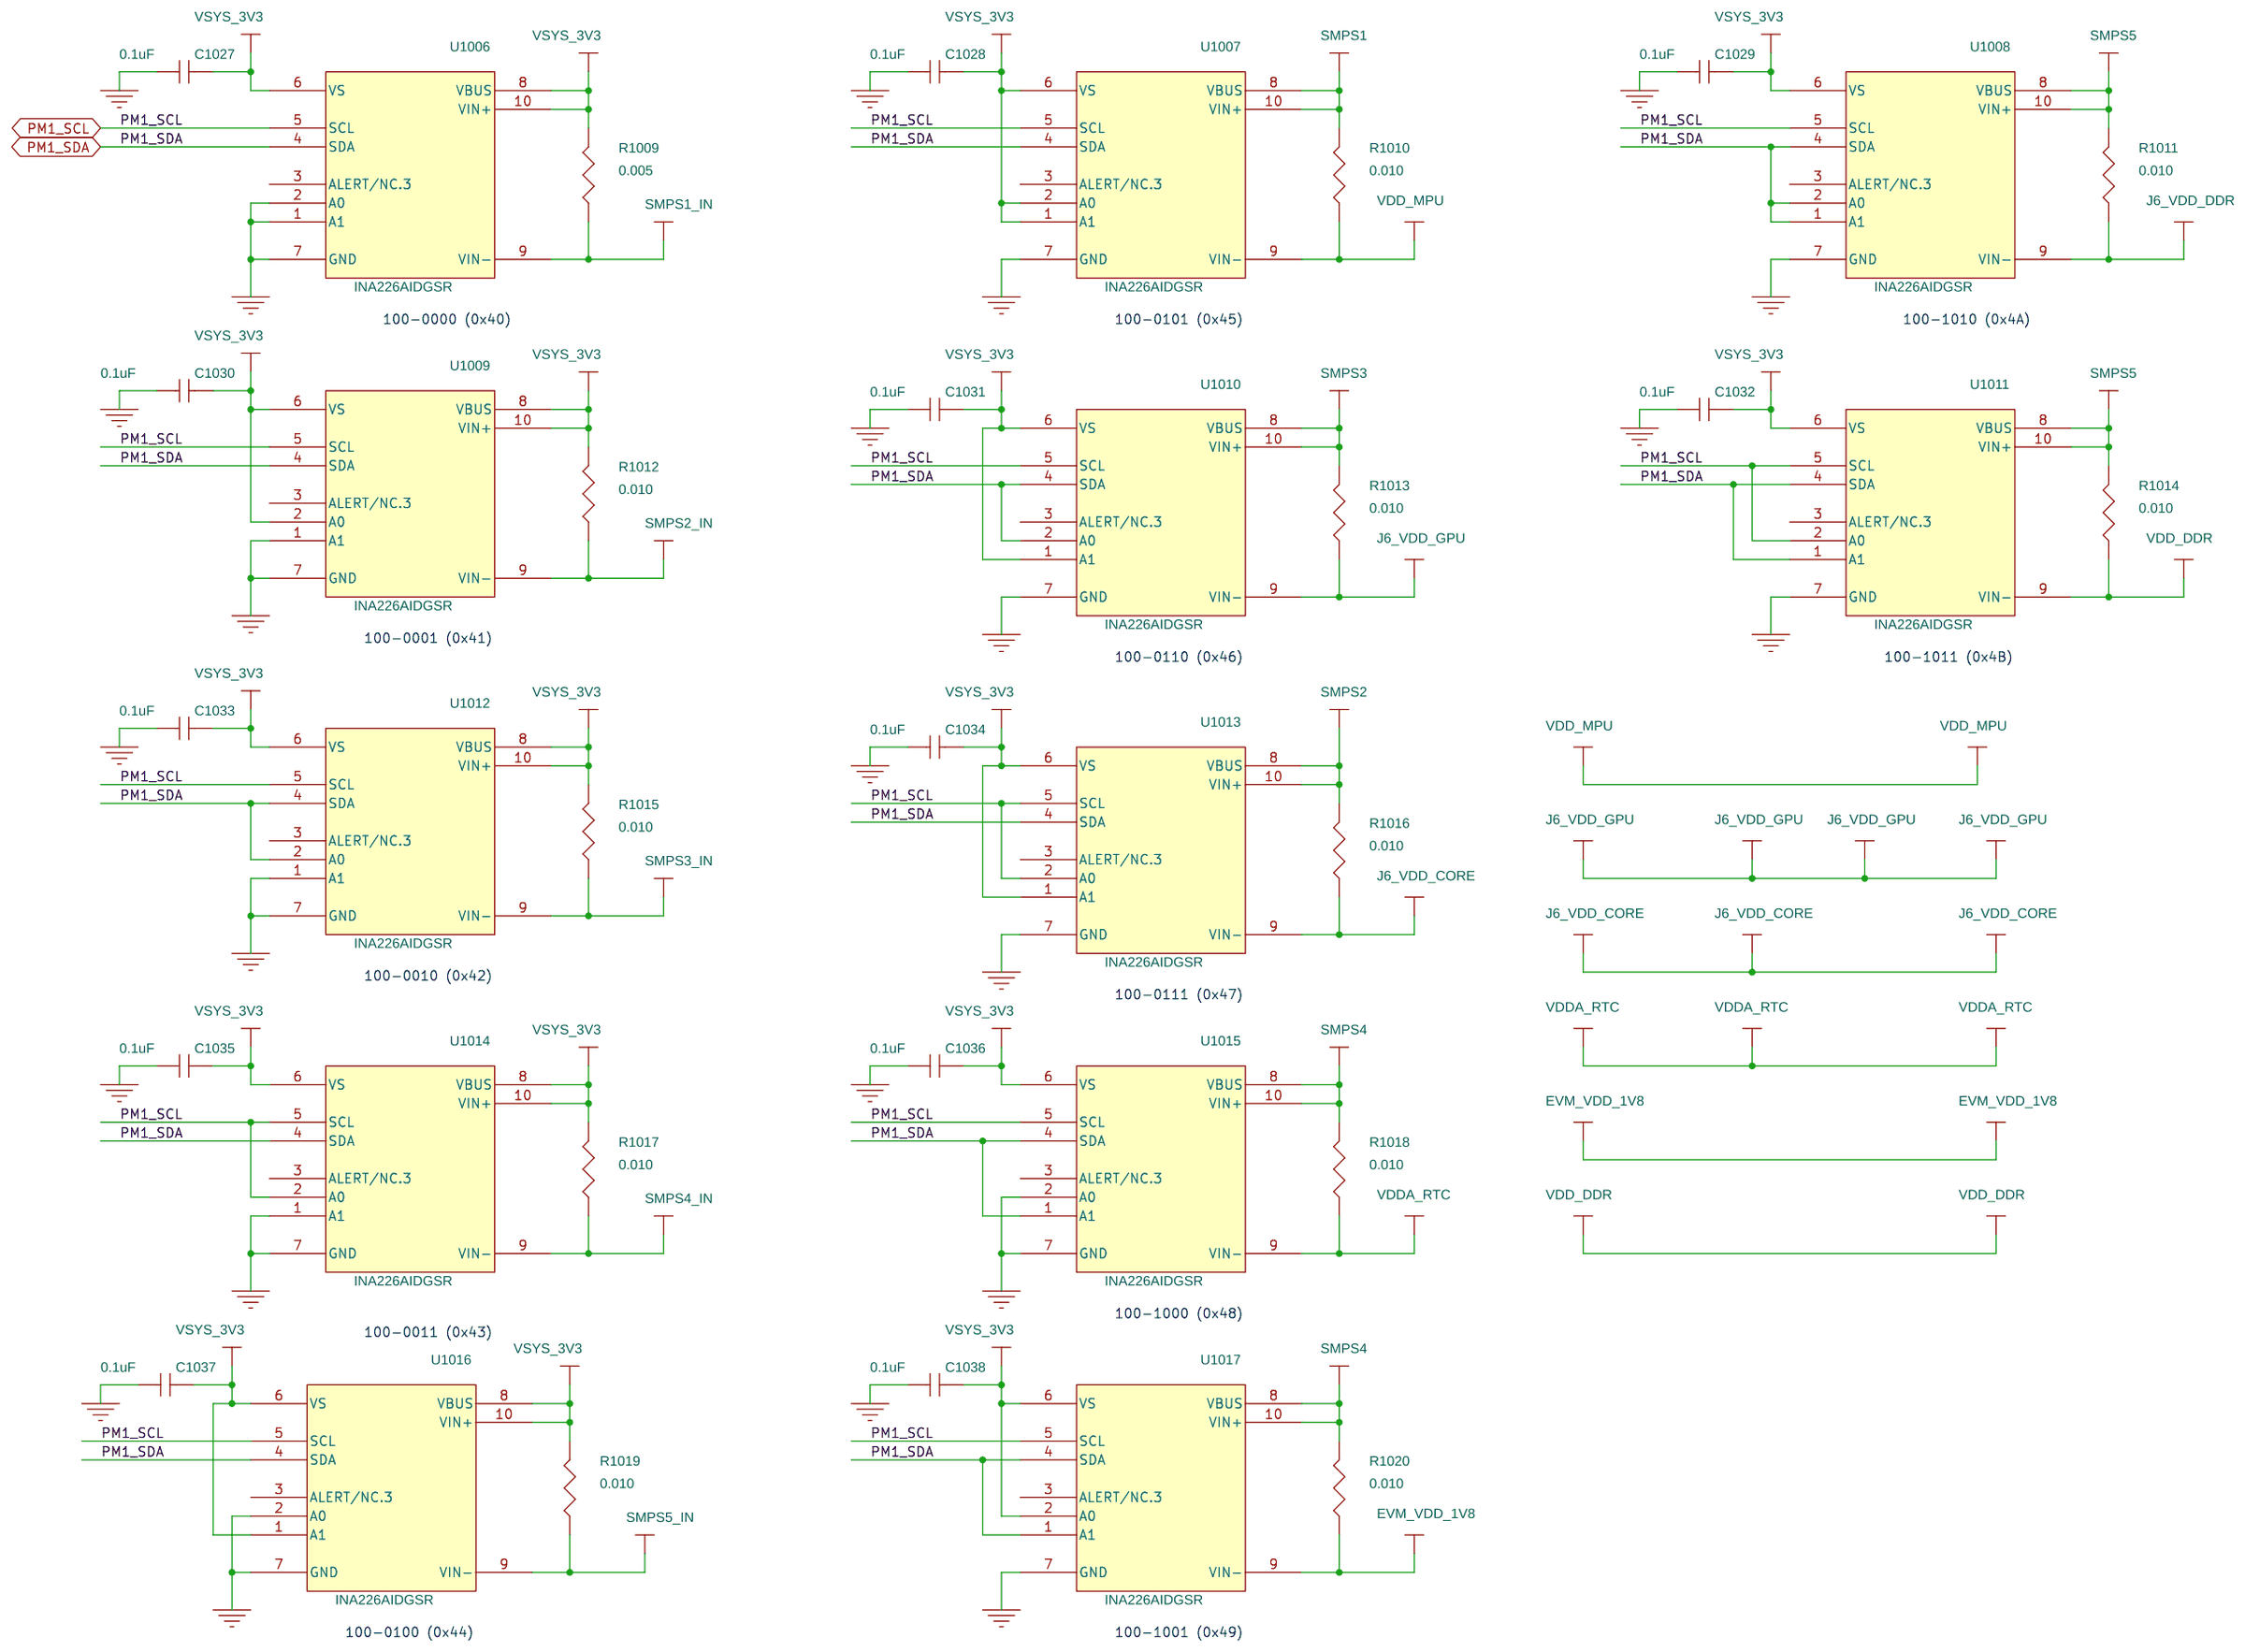
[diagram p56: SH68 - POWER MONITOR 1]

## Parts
sheet SH58 - ETHERNET PORT0
C1077  .01uF  [c402-25]
C1078  1000pF  [c402-25]
C1079  1000pF  [c402-25]
C1080  27 pF  [c603-35x45]
C1081  .01uF  [c402-25]
C1082  10uF  [c603-35x45]
C1083  1000pF  [c402-25]
C1084  1000pF  [c402-25]
C1085  10uF  [c603-35x45]
C1086  1000pF  [c402-25]
C1087  27 pF  [c603-35x45]
C1088  1000pF  [c402-25]
C1089  1000pF  [c402-25]
C1090  0.1uF  [c402-25]
C1091  1000pF  [c402-25]
C1092  10uF  [c603-35x45]
C1093  .01uF  [c402-25]
C1094  1000pF  [c402-25]
C1095  .01uF  [c402-25]
P5  6605814-6  [amp-6605814]
R1113  NP  [r402-25]
R1114  NP  [r402-25]
R1115  NP  [r402-25]
R1116  NP  [r402-25]
R1117  NP  [r402-25]
R1118  5.6K  [r402-25]
R1119  NP  [r402-25]
R1120  NP  [r402-25]
R1121  NP  [r402-25]
R1122  NP  [r402-25]
R1123  NP  [r402-25]
R1124  2.49K  [r402-25]
R1125  220  [r402-25]
R1126  220  [r402-25]
R1127  2K  [r402-25]
R1128  NO-POP  [r402-25]
R1129  2K  [r402-25]
R1132  11K 1%  [r402-25]
R1134  NP  [r402-25]
R1135  NP  [r402-25]
R1136  NP  [r402-25]
R1137  NP  [r402-25]
RJ4  0  [JMP402-25]
TP1024  TP  [tp-30RD13]
U10  74LVC1G08DCK  [dck-5]
U1037  DP83867IRPAP  [pap64-12x70]
Y10  25MHz  [xtal2-75x94]
sheet SH59 - ETHERNET PORT1
C37  .01uF  [c402-25]
C43  0.1uF  [c402-25]
C224  .01uF  [c402-25]
C237  10uF  [c603-35x45]
C240  .01uF  [c402-25]
C246  1000pF  [c402-25]
C247  1000pF  [c402-25]
C248  1000pF  [c402-25]
C249  1000pF  [c402-25]
C250  27 pF  [c603-35x45]
C258  27 pF  [c603-35x45]
C260  1000pF  [c402-25]
C263  1000pF  [c402-25]
C270  1000pF  [c402-25]
C281  10uF  [c603-35x45]
C282  10uF  [c603-35x45]
C283  .01uF  [c402-25]
C284  1000pF  [c402-25]
C289  1000pF  [c402-25]
P6  6605814-6  [amp-6605814]
R296  220  [r402-25]
R297  220  [r402-25]
R348  11K 1%  [r402-25]
R355  2K  [r402-25]
R357  2K  [r402-25]
R359  NP  [r402-25]
R361  NP  [r402-25]
R362  NP  [r402-25]
R366  NP  [r402-25]
R369  NP  [r402-25]
R373  NP  [r402-25]
R380  NP  [r402-25]
R386  NP  [r402-25]
R387  NO-POP  [r402-25]
R399  2K  [r402-25]
R435  NP  [r402-25]
R441  NP  [r402-25]
R447  NP  [r402-25]
R1138  NP  [r402-25]
R1139  NP  [r402-25]
R1140  NP  [r402-25]
R1141  NP  [r402-25]
RJ3  0  [JMP402-25]
TP1023  TP  [tp-30RD13]
U84  DP83867IRPAP  [pap64-12x70]
U85  74LVC1G08DCK  [dck-5]
Y7  25MHz  [xtal2-75x94]
sheet SH60 - APPLICATION IF CONN1
EXP_P1  QSE-020-01-L-D-A-K  [QSE_020]
R480  10K  [r402-25]
ZJ1  TestPoint1_0  [mhp125-250]
ZJ2  MNTHOLE  [mhp125-250]
ZJ3  MNTHOLE  [mhp125-250]
ZJ4  MNTHOLE  [mhp125-250]
sheet SH61 - APPLICATION IF  CONN2
EXP_P2  QSE-060-01-L-D-A-K  [qse-060-0x-x-d-a]
R1099  NP  [r402-25]
TP7  TestPoint1  [tp1-18rd8]
TP8  TestPoint1  [tp1-18rd8]
TP9  TestPoint1  [tp1-18rd8]
TP10  TestPoint1  [tp1-18rd8]
TP11  TestPoint1  [tp1-18rd8]
TP12  TestPoint1  [tp1-18rd8]
TP13  TestPoint1  [tp1-18rd8]
TP14  TestPoint1  [tp1-18rd8]
TP15  TestPoint1  [tp1-18rd8]
sheet SH62 - APPLICATION IF  CONN3
C1076  0.1uF  [c402-25]
EXP_P3  QSE-020-01-L-D-A-K  [QSE_020]
R1133  10K  [r201-6p6spc]
RU117  SN74CBTLV3257PW  [tssop16-14x70]
TP16  TP_0  [tp1-18rd8]
TP17  TP_0  [tp1-18rd8]
TP18  TP_0  [tp1-18rd8]
TP19  TP_0  [tp1-18rd8]
TP20  TP_0  [tp1-18rd8]
TP21  TP_0  [tp1-18rd8]
TP25  TP_0  [tp1-18rd8]
TP26  TP_0  [tp1-18rd8]
TP28  TP_0  [tp1-18rd8]
TP29  TP_0  [tp1-18rd8]
TP33  TP_0  [tp1-18rd8]
TP34  TP_0  [tp1-18rd8]
TP35  TP_0  [tp1-18rd8]
TP36  TP_0  [tp1-18rd8]
TP66  TP_0  [tp1-18rd8]
sheet SH63 - RESET
C421  220pF  [c402-25]
C441  0.1uF  [c402-25]
C476  220pF  [c402-25]
C499  0.1uF  [c402-25]
C1097  220pF  [c402-25]
C1098  220pF  [c402-25]
R554  0  [r402-25]
R555  NO-P0P  [r402-25]
R583  10K  [r402-25]
R596  10K  [r402-25]
R616  10K  [r402-25]
R623  10K  [r402-25]
R1037  0  [r402-25]
R9357  0  [r402-25]
R9358  0  [r402-25]
SW4  PB_SW  [SW4-7914G]
SW6  PB_SW  [SW4-7914G]
U102  TPS3808G09DBVRG4  [DBV6-27X39-6]
U107  TPS3808G09DBVRG4  [DBV6-27X39-6]
sheet SH64 - POWER INPUT
C45  0.1uF  [c603-35x45]
C47  1uF  [c805-35x60]
C49  0.1uF  [c603-35x45]
C50  1uF  [c805-35x60]
C52  4.7uF  [c1210-70x102]
C706  2.2uF 25V X7R  [c805-35x60]
C707  0.22uF  [c603-35x45]
D1  SMCJ30A-13-F  [SMC-80X128]
D2  SMCJ14A-13-F  [SMC-80X128]
DS5  LED_GRN  [led1206-59x59]
F1  8A_QuickBlow  [FUSEFOLDER-OMNI-BLOK]
J3  PJ-063BH  [pwrjack-cui-pj063bh]
J4  HEADER 2  [JUMP1X2-6040]
J7  HEADER 2  [JUMP1X2-6040]
Q5  CSD18501Q5A  [pwr-q5a-slps319]
R775  1K  [r402-25]
R810  1K  [r402-25]
SW9  PB_SW  [SW4-7914G]
TP3  TESTPOINT  [tp1-6040]
TP4  TESTPOINT  [tp1-6040]
TP62  TESTPOINT  [tp1-6040]
TP63  TESTPOINT  [tp1-6040]
TP823  SMT-TP  [TP1-70X135]
TP824  SMT-TP  [TP1-70X135]
TP825  SMT-TP  [TP1-70X135]
TP826  SMT-TP  [TP1-70X135]
TP827  SMT-TP  [TP1-70X135]
TP828  SMT-TP  [TP1-70X135]
TP829  SMT-TP  [TP1-70X135]
TP830  SMT-TP  [TP1-70X135]
TP831  TP_0  [tp1-18rd8]
U8  LM74610  [dgk8-14x70]
sheet SH65 - POWER TPS443351DAP
C51  100uF,25V  [c7343-84x118]
C60  330pF  [c603-35x45]
C61  330pF  [c603-35x45]
C62  22uF,25V, x5R  [c1210-70x102]
C63  22uF,25V, x5R  [c1210-70x102]
C71  100uF 10V  [c7343-84x118]
C72  47UF 16V  [c1210-c7343-dual]
C74  100uF 10V  [c7343-84x118]
C76  100pF  [c603-35x45]
C77  47UF 16V  [c1210-c7343-dual]
C78  100pF  [c603-35x45]
C295  4.7uF/25V  [c805-35x60]
C299  .22uF,50V  [c603-35x45]
C300  .22uF,50V  [c603-35x45]
C301  .01uF  [c402-25]
C302  .01uF  [c402-25]
C303  2000pF  [c402-25]
C304  39pf  [c402-25]
C305  .01uF  [c402-25]
C306  .01uF  [c402-25]
C307  2700pF  [c402-25]
C309  56pf  [c402-25]
C314  1000pF  [c402-25]
C683  100uF 10V  [c7343-84x118]
C684  NO-POP  [c1210-70x102]
C689  100uF 10V  [c7343-84x118]
C690  100uF 10V  [c7343-84x118]
L6  2.2uH ( 7443330220)  [choke-power-we-hcc]
L7  8.2uH(744771008 )  [ind2-115x213-12mm]
Q1  CSD18501Q5A  [pwr-q5a-slps319]
Q2  CSD18501Q5A  [pwr-q5a-slps319]
Q3  CSD18501Q5A  [pwr-q5a-slps319]
Q4  CSD18501Q5A  [pwr-q5a-slps319]
R12  0  [r402-25]
R13  0  [r402-25]
R126  10  [r603-35X45]
R127  10  [r603-35X45]
R134  0.005  [r2725-125x250]
R135  0.015  [R2512]
R138  NP  [r402-25]
R140  NP  [r402-25]
R141  NO-POP  [r402-25]
R142  NO-POP  [r402-25]
R143  49.9  [r603-35x45]
R144  49.9K 1%  [r603-35x45]
R145  16K 1%  [r603-35x45]
R146  84.5K 1%  [r603-35x45]
R147  49.9  [r603-35x45]
R450  0  [r402-25]
R451  0  [r402-25]
R453  1.5K  [r603-35x45]
R454  NO-POP  [r402-25]
R455  0  [r402-25]
R456  0  [r402-25]
R457  0  [r402-25]
R461  20K  [r402-25]
R463  0  [r402-25]
R464  15K  [r402-25]
R472  16K 1%  [r603-35x45]
U23  TPS43351QDAPRQ1  [dap38]
sheet SH66 - MISC POWER SWITCHES
C174  10uF  [C1206-40X70]
C179  10pF  [c402-25]
C186  1000pF  [c402-25]
C187  0.001uF  [c402-25]
C188  10uF  [C1206-40X70]
C191  10uF  [C1206-40X70]
C192  10uF  [C1206-40X70]
C201  10uF  [C1206-40X70]
C202  10uF  [C1206-40X70]
C318  220pF 50V  [c603-35x45]
C319  NO-POP  [c603-35x45]
C607  0.1uF  [c402-25]
C658  0.1uF  [c402-25]
C659  0.1uF  [c402-25]
C702  220pF 50V  [c603-35x45]
Q6  NTA4153N  [SC-75]
Q7  AO3404A(or BSS138)  [SOT23-28X44-GSD]
R273  10K  [r402-25]
R282  100K  [r402-25]
R283  10K  [r402-25]
R290  10  [r402-25]
R291  10.0K  [r402-25]
R292  10.0K  [r402-25]
R293  0.025  [R2512]
R473  10K  [r603-35x45]
R803  NP  [r402-25]
R808  0  [r402-25]
R822  NP  [r1206-40X70]
R826  0  [r402-25]
R827  10K  [r402-25]
TP64  TEST POINT  [tp1-6040]
TP65  TEST POINT  [tp1-6040]
U64  TPS51200  [drc10-11x33]
U92  TPS22965DSG  [dsg8-11x20]
U138  TPS22965DSG  [dsg8-11x20]
sheet SH67 - PMIC
C1001  10uF 6.3V  [C805-35X60]
C1002  10uF 6.3V  [C805-35X60]
C1003  100nF 16V  [c402-25]
C1004  2.2uF 6.3V  [c603-35x45]
C1005  2.2uF 6.3V  [c603-35x45]
C1007  100nF 16V  [c402-25]
C1008  4.7uF 10V  [C805-35X60]
C1009  4.7uF 10V  [C805-35X60]
C1010  4.7uF 10V  [C805-35X60]
C1011  4.7uF 10V  [C805-35X60]
C1012  4.7uF 10V  [C805-35X60]
C1013  47uF 10V  [C1210-70x102]
C1014  47uF 10V  [C1210-70x102]
C1015  47uF 10V  [C1210-70x102]
C1016  47uF 10V  [C1210-70x102]
C1017  47uF 10V  [C1210-70x102]
C1018  2.2uF 6.3V  [c603-35x45]
C1019  2.2uF 6.3V  [c603-35x45]
C1020  2.2uF 6.3V  [c603-35x45]
C1021  2.2uF 6.3V  [c603-35x45]
C1022  2.2uF 6.3V  [c603-35x45]
C1023  2.2uF 6.3V  [c603-35x45]
C1024  2.2uF 6.3V  [c603-35x45]
C1025  2.2uF 6.3V  [c603-35x45]
C1026  2.2uF 6.3V  [c603-35x45]
J1001  PM5  [JUMP1X5-6040]
L1001  1uH  [ind2-65x90-ihlp1616]
L1002  1uH  [ind2-65x90-ihlp1616]
L1003  1uH  [ind2-65x90-ihlp1616]
L1004  1uH  [ind2-65x90-ihlp1616]
L1005  1uH  [ind2-65x90-ihlp1616]
R483  NP  [r201-6p6spc]
R516  0  [r201-6p6spc]
R589  2K  [r402-25]
R797  1.74K  [r402-25]
R1005  2.2k  [r402-25]
R1006  2.2k  [r402-25]
R1007  2.2k  [r402-25]
R1008  2.2k  [r402-25]
R1076  NP  [r402-25]
R1077  0  [r402-25]
SW7  PB_SW  [SW4-7914G]
TP1009  NP  [tp-30RD13]
TP1010  NP  [tp-30RD13]
TP1011  NP  [tp-30RD13]
TP1015  NP  [tp-30RD13]
TP1016  NP  [tp-30RD13]
TP1017  NP  [tp-30RD13]
TP1018  NP  [tp-30RD13]
U1001  PO917A13DTRGZRQ1  [rgz48-11x34]
U1005  TPD4E002  [drl5-12x40]
sheet SH68 - POWER MONITOR 1
C1027  0.1uF  [c402-25]
C1028  0.1uF  [c402-25]
C1029  0.1uF  [c402-25]
C1030  0.1uF  [c402-25]
C1031  0.1uF  [c402-25]
C1032  0.1uF  [c402-25]
C1033  0.1uF  [c402-25]
C1034  0.1uF  [c402-25]
C1035  0.1uF  [c402-25]
C1036  0.1uF  [c402-25]
C1037  0.1uF  [c402-25]
C1038  0.1uF  [c402-25]
R1009  0.005  [r1206-40X70]
R1010  0.010  [r1210-70x102]
R1011  0.010  [r1206-40X70]
R1012  0.010  [r1206-40X70]
R1013  0.010  [r1210-70x102]
R1014  0.010  [r1206-40X70]
R1015  0.010  [r1206-40X70]
R1016  0.010  [r1206-40X70]
R1017  0.010  [r1206-40X70]
R1018  0.010  [r1206-40X70]
R1019  0.010  [r1206-40X70]
R1020  0.010  [r1206-40X70]
U1006  INA226AIDGSR  [dgs10-11x60]
U1007  INA226AIDGSR  [dgs10-11x60]
U1008  INA226AIDGSR  [dgs10-11x60]
U1009  INA226AIDGSR  [dgs10-11x60]
U1010  INA226AIDGSR  [dgs10-11x60]
U1011  INA226AIDGSR  [dgs10-11x60]
U1012  INA226AIDGSR  [dgs10-11x60]
U1013  INA226AIDGSR  [dgs10-11x60]
U1014  INA226AIDGSR  [dgs10-11x60]
U1015  INA226AIDGSR  [dgs10-11x60]
U1016  INA226AIDGSR  [dgs10-11x60]
U1017  INA226AIDGSR  [dgs10-11x60]

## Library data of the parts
C37 C224 C240 C283 C301 C302 C305 C306 C1077 C1081 C1093 C1095 = CAP: Part #: 101587-1101R
C246-C249 C260 C263 C270 C284 C289 C1078 C1079 C1083 C1084 C1086 C1088 C1089 C1091 C1094 = CAP: Part #: 102058-1102R
C250 C258 C1080 C1087 = CAP_NP_3: Part #: 101103-1274R
C237 C281 C282 C1082 C1085 C1092 = CAP: Part #: 102963-0101R
C43 C1090 = CAP: Part #: 101587-1100R
P5 P6 = 66058414_1: Part #: 103166-0001R
R141 R142 R359 R361 R362 R366 R369 R373 R380 R386 R387 R435 R441 R447 R803 R1076 R1099 R1113-R1117 R1119-R1123 R1128 R1134-R1141 = R: Part #: R0402-NOPOP
R1118 = R: Part #: 102145-5602R
R1124 = R: Part #: 102145-2492R
R296 R297 R1125 R1126 = RES_0: Part #: 101370-2201R
R355 R357 R399 R1127 R1129 = R: Part #: 102145-2002R
R348 R1132 = R: Part #: 102145-1103R
RJ3 RJ4 = RJUMP3: Part #: 101370-0001R
TP1009-TP1011 TP1015-TP1018 TP1023 TP1024 = TESTPOINT: Part #: TP-30RD13-NO-POP
U10 U85 = 1G08: Part #: 101057-0008R
U84 U1037 = DP83867IR: Part #: 104742-0001R
Y7 Y10 = CRYSTAL_0_v2: Part #: 101590-0250R
EXP_P1 EXP_P3 = J_-_SamTec_QSH020_40pin_2: Part #: 101881-0020R
R273 R283 R480 R827 = R: Part #: 101370-1003R
ZJ1-ZJ4 = TestPoint1_0: Part #: NO-POP
EXP_P2 = J_-_SamTec_QSH060_120pin_2: Part #: 101881-0060R
TP7-TP15 = TestPoint1_0: Part #: TP-18RD8-NO-POP
C607 C658 C659 C1027-C1038 C1076 = CAP_NP: Part #: 101587-1100R
R1133 = R: Part #: 103158-1003R
RU117 = SN74CBT3257PW_0: Part #: 101670-0001R
TP16-TP21 TP25 TP26 TP28 TP29 TP33-TP36 TP66 TP831 = TP_0: Part #: TP-18RD8-NO-POP
C421 C476 C1097 C1098 = CAP_NP_2: Part #: 101782-1223R
C441 C499 = CAP_NP_2: Part #: 101587-1100R
R12 R13 R554 R808 R826 R1037 R1077 R9357 R9358 = R: Part #: 101370-0001R
R555 = R_2: Part #: R0402-NOPOP
R583 R616 = RESISTOR: Part #: 101370-1003R
R596 R623 = R_2: Part #: 101370-1003R
SW4 SW6 SW7 SW9 = SW_PUSHBUTTON_3: Part #: 101023-0001R
U102 U107 = TPS3808G09DBVR_0: Part #: 102020-0009R
C45 C49 = CAP_NP: Part #: 100993-1100R
C47 C50 = CAP_NP: Part #: 100201-0100R
C52 = CAP_NP: Part #: 103058-0470R
C706 = CAP_NP_0: Part #: 101415-0220R
C299 C300 C707 = CAP: Part #: 103885-1220R
D1 = Diode_SMCJ15CA: Part #: 101808-0030R
D2 = Diode_SMCJ15CA: Part #: 101808-0014R
DS5 = LED_RED_0: Part #: 100823-0001R
F1 = NANO-SMF_0: Part #: 102110-0008R
J3 = PWR_JACK_0: Part #: 104303-0001R
J4 J7 = HEADER_2: Part #: 100115-0002R
Q1-Q5 = MOSFET_CSD16406Q3_0: Part #: 104283-0001R
R775 R810 = R_2: Part #: 102145-1002R
TP3 TP4 TP62 TP63 = TESTPOINT: Part #: 100115-0001R
TP823-TP830 = SMT-TP: Part #: 104178-0001R
U8 = LM74610: Part #: 104635-0001R
C51 = CAP_POL: Part #: 104700-0102R
C60 C61 = CAP: Part #: 100993-3303R
C62 C63 = CAP_NP: Part #: 104292-0221R
C71 C74 C683 C689 C690 = C_0: Part #: 104290-0102R
C72 C77 = CAP: Part #: 104294-0471R
C76 C78 = CAP: Part #: 100993-1103R
C295 = CAP: Part #: 103751-0470R
C303 = CAP: Part #: 104291-1202R
C304 = CAP: Part #: 101782-1394R
C307 = CAP: Part #: 102058-1272R
C309 = CAP: Part #: 101782-1564R
C314 = CAP: Part #: 101782-1102R
C684 = CAP: pART #: C1210-NOPOP
L6 = INDUCTOR: Part #: 104227-0220R
L7 = INDUCTOR: Part #: 104288-0820R
R126 R127 = RESISTOR: Part #: 100687-1000R
R134 = RESISTOR: Part #: 104280-0005R
R135 = RESISTOR: Part #: 100830-0015R
R138 R140 R454 = RESISTOR: Part #: R0402-NOPOP
R143 R147 = RESISTOR: Part #: 100642-4990R
R144 = RESISTOR: Part #: 100642-4993R
R145 R472 = RESISTOR: Part #: 102145-1603R
R146 = RESISTOR: Part #: 100642-8453R
R450 R451 R455-R457 R463 = RESISTOR: Part #: 101370-0001R
R453 = RESISTOR: Part #: 100687-1502R
R461 = RESISTOR: Part #: 102145-2003R
R464 = RESISTOR: Part #: 102145-1503R
U23 = TPS43351QDAPRQ1_0: Part #: 104224-0001R
C174 C188 C191 C192 C201 C202 = CAP_NP: Part #: 101497-0101R
C179 = CAP_NP: Part #: 101782-1104R
C186 C187 = CAP_NP: Part #: 102058-1102R
C318 C702 = CAP: Part #: 100993-1223R
C319 = CAP: Part #: C0603-NOPOP
Q6 = NTA4153N: Part #: 102437-0001R
Q7 = MOSFET_N_0: Part #: 102159-0001R
R282 = R: Part #: 101370-1004R
R290 = R: Part #: 101370-1000R
R291 R292 = R: Part #: 102145-1003R
R293 = R: Part #: 100830-0025R
R473 = RESISTOR: Part #: 100687-1003R
R822 = R: Part #: r1206-nopop
TP64 TP65 = TEST_POINT: Part #: 100115-0001R
U64 = TPS51200: Part #: 103316-0001R
U92 U138 = TPS22965DSG: Part #: 104267-0001R
C1001 C1002 = C_10uF_6.3V_X5R_0603: Distributor ref: 1288201; Part #: 104447-0101R
C1003 C1007 = C_10uF_6.3V_X5R_0603: Distributor ref: 1288201; Part #: 104446-1100R
C1004 C1005 C1018-C1026 = C_2.2uF_0402_6.3V_X5R_0402: Part #: 104448-0220R
C1008-C1012 = C_4.7uF_0402_6.3V_X5R_0402: Part #: 101063-0470R
C1013-C1017 = C_10uF_6.3V_X5R_0603: Distributor ref: 1288201; Part #: 104247-0471R
J1001 = HEADER_5: Part #: 100115-0005R
L1001-L1005 = IND_1.47uH_DFE252012C_R47N: Manufacturer ref: IHLP-1616ABER1R0M11; Part #: 104246-0100R
R483 = R_10K_0402_1%_Multi: Part #: r0201-nopop
R516 = R_10K_0402_1%_Multi: Part #: 103158-0001R
R589 = R_10K_0402_1%_Multi: Part #: 102145-2002R
R797 = R: Part #: 102145-1742R
R1005-R1008 = R: Part #: 101370-2202R
U1001 = TPS65917: Part #: 104443-0002R-TI
U1005 = TPD4E002: Part #: 103176-0001R
R1009 = R: Part #: 104444-0005R
R1010-R1020 = R: Part #: 102598-0001R
U1006-U1017 = INA220IDCN_2: Part #: 103928-0001R

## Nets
GND: C37.2 C43.2 C45.2 C47.2 C49.2 C50.2 C51.2 C52.2 C60.1 C61.1 C62.1 C63.1 C71.2 C72.2 C74.2 C76.1 C77.2 C78.1 C174.1 C179.1 C186.1 C187.1 C188.1 C191.1 C192.1 C201.1 C202.1 C224.2 C237.2 C240.2 C246.2 C247.2 C248.2 C249.2 C250.2 C258.2 C260.2 C263.2 C270.2 C281.2 C282.2 C283.2 C284.2 C289.2 C295.1 C304.1 C305.2 C306.2 C309.1 C314.2 C318.2 C319.2 C421.2 C441.2 C476.2 C499.2 C607.1 C658.1 C659.1 C683.2 C684.2 C689.2 C690.2 C702.2 C707.2 C1001.2 C1002.2 C1003.2 C1004.2 C1005.2 C1007.1 C1008.1 C1009.1 C1010.1 C1011.1 C1012.1 C1013.1 C1014.1 C1015.1 C1016.1 C1017.1 C1018.1 C1019.1 C1020.1 C1021.1 C1022.1 C1023.1 C1024.1 C1025.1 C1026.1 C1027.1 C1028.1 C1029.1 C1030.1 C1031.1 C1032.1 C1033.1 C1034.1 C1035.1 C1036.1 C1037.1 C1038.1 C1076.2 C1077.2 C1078.2 C1079.2 C1080.2 C1081.2 C1082.2 C1083.2 C1084.2 C1085.2 C1086.2 C1087.2 C1088.2 C1089.2 C1090.2 C1091.2 C1092.2 C1093.2 C1094.2 C1095.2 C1097.2 C1098.2 D2.1(CATHODE) DS5.1(cathode) EXP_P1.2 EXP_P1.4 EXP_P1.10 EXP_P1.19 EXP_P1.20 EXP_P1.29 EXP_P1.30 EXP_P1.39 EXP_P1.40 EXP_P1.41(G1) EXP_P1.42(G2) EXP_P1.43(G3) EXP_P1.44(G4) EXP_P2.26 EXP_P2.27 EXP_P2.77 EXP_P2.78 EXP_P2.115 EXP_P2.116 EXP_P2.121(G1) EXP_P2.122(G2) EXP_P2.123(G3) EXP_P2.124(G4) EXP_P2.125(G5) EXP_P2.126(G6) EXP_P2.127(G7) EXP_P2.128(G8) EXP_P2.129(G9) EXP_P2.130(G10) EXP_P2.131(G11) EXP_P2.132(G12) EXP_P3.19 EXP_P3.20 EXP_P3.41(G1) EXP_P3.42(G2) EXP_P3.43(G3) EXP_P3.44(G4) J3.2 J3.MTG1 J3.MTG2 J4.1 J7.2 J1001.3 P5.1(GND) P5.11(SHLD1) P5.12(SHLD2) P5.D4(LED2-KA) P6.1(GND) P6.11(SHLD1) P6.12(SHLD2) P6.D4(LED2-KA) Q3.1(S1) Q3.2(S2) Q3.3(S3) Q4.1(S1) Q4.2(S2) Q4.3(S3) Q6.2(S) Q7.S R145.1 R291.1 R348.1 R359.2 R361.2 R366.1 R369.1 R380.1 R386.2 R399.1 R455.1 R461.1 R463.1 R464.1 R472.1 R483.1 R555.1 R589.2 R803.1 R810.2 R1113.2 R1115.1 R1116.1 R1122.1 R1123.2 R1124.2 R1127.1 R1132.1 R1134.2 R1136.2 R1138.2 R1140.2 RJ3.1 RJ4.1 RU117.8(GND) RU117.15(~{OE}) SW4.1(A) SW4.2(AA) SW6.1(A) SW6.2(AA) SW7.1(A) SW7.2(AA) TP3.1(TP) TP4.1(TP) TP62.1(TP) TP63.1(TP) TP823.1 TP824.1 TP825.1 TP826.1 TP827.1 TP828.1 TP829.1 TP830.1 U10.3(GND) U23.9(PGNDA) U23.19(AGND.1) U23.23(AGND.2) U23.30(PGNDB) U23.39(PWR_PAD) U64.4(PGND) U64.8(GND) U64.11(PWRPAD) U84.65(GND) U85.3(GND) U92.5(GND) U92.9(PWR_PAD) U102.2(GND) U107.2(GND) U138.5(GND) U138.9(PWR_PAD) U1001.20(VPROG) U1001.41(REFGND) U1001.49(PAD) U1005.2(GND) U1006.1(A1) U1006.2(A0) U1006.7(GND) U1007.7(GND) U1008.7(GND) U1009.1(A1) U1009.7(GND) U1010.7(GND) U1011.7(GND) U1012.1(A1) U1012.7(GND) U1013.7(GND) U1014.1(A1) U1014.7(GND) U1015.2(A0) U1015.7(GND) U1016.2(A0) U1016.7(GND) U1017.7(GND) U1037.65(GND) ; also on sheet 3 5 7 10 11 12 13 14 15 16 17 18 20 21 22 23 24 25 26 27 28 29 30 31 32 33 34 35 36 37 38 39 40 41 42 43 44 45 46 58 59 62 63 64 65 66 67 68 69 70 71
VCCA_IN: C1002.1 U1001.42(VCCA) ; also on sheet 58
VIN1A_CLK0: EXP_P2.61 ; also on sheet 68
VIN1A_D0: EXP_P2.79 ; also on sheet 63
VIN1A_D1: EXP_P2.80 ; also on sheet 63
VIN1A_D2: EXP_P2.81 ; also on sheet 63
VIN1A_D3: EXP_P2.82 ; also on sheet 63
VIN1A_D4: EXP_P2.83 ; also on sheet 63
VIN1A_D5: EXP_P2.84 ; also on sheet 63
VIN1A_D6: EXP_P2.87 ; also on sheet 63
VIN1A_D7: EXP_P2.88 ; also on sheet 63
VIN1A_D8: EXP_P2.89 ; also on sheet 63
VIN1A_D9: EXP_P2.90 ; also on sheet 63
VIN1A_D10: EXP_P2.91 ; also on sheet 63
VIN1A_D11: EXP_P2.92 ; also on sheet 63
VIN1A_D12: EXP_P2.93 ; also on sheet 63
VIN1A_D13: EXP_P2.94 ; also on sheet 63
VIN1A_D14: EXP_P2.95 ; also on sheet 63
VIN1A_D15: EXP_P2.96 ; also on sheet 63
VIN1A_D16: EXP_P2.97 ; also on sheet 63
VIN1A_D17: EXP_P2.98 ; also on sheet 63
VIN1A_D18: EXP_P2.109 ; also on sheet 63
VIN1A_D19: EXP_P2.110 ; also on sheet 63
VIN1A_D20: EXP_P2.111 ; also on sheet 63
VIN1A_D21: EXP_P2.112 ; also on sheet 63
VIN1A_D22: EXP_P2.113 R1099.2 ; also on sheet 63
VIN1A_D23: EXP_P2.114 ; also on sheet 63
VIN1A_DE0: EXP_P2.63 ; also on sheet 68
VIN1A_HSYNC0: EXP_P2.62 ; also on sheet 68
VIN1A_VSYNC0: EXP_P2.64 ; also on sheet 68
VIN[2]A_CLK: EXP_P2.48 ; also on sheet 25
VIN[2]A_D[0]: EXP_P2.40 ; also on sheet 25
VIN[2]A_D[1]: EXP_P2.41 ; also on sheet 25
VIN[2]A_D[2]: EXP_P2.42 ; also on sheet 25
VIN[2]A_D[3]: EXP_P2.43 ; also on sheet 25
VIN[2]A_D[4]: EXP_P2.44 ; also on sheet 25
VIN[2]A_D[5]: EXP_P2.45 ; also on sheet 25
VIN[2]A_D[6]: EXP_P2.46 ; also on sheet 25
VIN[2]A_D[7]: EXP_P2.47 ; also on sheet 25
VIN[2]A_D[8]: EXP_P2.68 ; also on sheet 25
VIN[2]A_D[9]: EXP_P2.67 ; also on sheet 25
VIN[2]A_D[10]: EXP_P2.70 ; also on sheet 25
VIN[2]A_D[11]: EXP_P2.69 ; also on sheet 25
VIN[2]A_D[12]: EXP_P2.72 ; also on sheet 25
VIN[2]A_D[13]: EXP_P2.71 ; also on sheet 25
VIN[2]A_D[14]: EXP_P2.74 ; also on sheet 25
VIN[2]A_D[15]: EXP_P2.73 ; also on sheet 25
VIN[2]A_D[16]: EXP_P2.3 ; also on sheet 25
VIN[2]A_D[17]: EXP_P2.4 ; also on sheet 25
VIN[2]A_D[18]: EXP_P2.5 ; also on sheet 25
VIN[2]A_D[19]: EXP_P2.6 ; also on sheet 25
VIN[2]A_D[20]: EXP_P2.7 ; also on sheet 25
VIN[2]A_D[21]: EXP_P2.8 ; also on sheet 25
VIN[2]A_D[22]: EXP_P2.9 ; also on sheet 25
VIN[2]A_D[23]: EXP_P2.10 ; also on sheet 25
VIN[2]A_DE0: EXP_P2.25 ; also on sheet 25
VIN[2]A_FLD0: EXP_P2.85 ; also on sheet 25
VIN[2]A_HSYNC: EXP_P2.1 ; also on sheet 25
VIN[2]A_VSYNC: EXP_P2.2 ; also on sheet 25
VIN[2]B_CLK1: EXP_P1.17 RU117.9(3A)
VIN[4]B_CLK1: EXP_P1.37 ; also on sheet 65
VIN[4]B_D[0]: EXP_P1.27 ; also on sheet 65
VIN[4]B_D[1]: EXP_P1.28 ; also on sheet 65
VIN[4]B_D[2]: EXP_P1.25 ; also on sheet 65
VIN[4]B_D[3]: EXP_P1.26 ; also on sheet 65
VIN[4]B_D[4]: EXP_P1.23 ; also on sheet 65
VIN[4]B_D[5]: EXP_P1.24 ; also on sheet 65
VIN[4]B_D[6]: EXP_P1.21 ; also on sheet 65
VIN[4]B_D[7]: EXP_P1.22 ; also on sheet 65
VIN[4]B_HSYNC1: EXP_P1.31 ; also on sheet 65
VIN[4]B_VSYNC1: EXP_P1.32 ; also on sheet 65
VIN[6]A_D[0]: EXP_P2.13 ; also on sheet 66
VIN[6]A_D[1]: EXP_P2.14 ; also on sheet 66
VIN[6]A_D[2]: EXP_P2.15 ; also on sheet 66
VIN[6]A_D[3]: EXP_P2.16 ; also on sheet 66
VIN[6]A_D[7]: EXP_P2.17 ; also on sheet 66
VIN[6]A_D[8]: EXP_P2.18 ; also on sheet 66
VIN[6]A_D[9]: EXP_P2.19 ; also on sheet 66
VIN[6]A_D[10]: EXP_P2.20 ; also on sheet 66
VIN[6]A_D[11]: EXP_P2.21 ; also on sheet 66
VIN[6]A_HSYNC: EXP_P2.11 ; also on sheet 66
VIN[6]A_VSYNC: EXP_P2.12 ; also on sheet 66
VIN_CONN: F1.2 J3.1 R453.2
APP_BD_PORz: EXP_P2.76 ; also on sheet 11
CORE_VDD: R1016.2 U1001.28(SMPS2_FDBK) U1013.9(VIN-) ; also on sheet 11 17 59
CPU_POR_RESETn: R596.1 U102.1(~{RESE}T) ; also on sheet 11
CPU_RESETn: R623.1 U107.1(~{RESE}T) ; also on sheet 11
CPU_VDD_DDR: R822.1 U138.7(VOUT.2) U138.8(VOUT.1) ; also on sheet 5 15
DDR_VREFSTL1: C607.2 U64.6(REFOUT) ; also on sheet 5 20 21
EMAC[0]_RXC: U1037.43(RX_CLK) ; also on sheet 65
EMAC[0]_RXCTL: R1136.1 R1137.1 U1037.53(RX_DV/RX_CTRL) ; also on sheet 65
EMAC[0]_RXD0: R1118.2 R1124.1 U1037.44(RX_D0) ; also on sheet 65
EMAC[0]_RXD1: U1037.45(RX_D1) ; also on sheet 65
EMAC[0]_RXD2: R1117.1 R1122.2 U1037.46(RX_D2) ; also on sheet 65
EMAC[0]_RXD3: U1037.47(RX_D3) ; also on sheet 65
EMAC[0]_TXC: U1037.40(GTX_CLK) ; also on sheet 65
EMAC[0]_TXCTL: U1037.52(TX_EN/TX_CTRL) ; also on sheet 65
EMAC[0]_TXD0: U1037.38(TX_D0) ; also on sheet 65
EMAC[0]_TXD1: U1037.37(TX_D1) ; also on sheet 65
EMAC[0]_TXD2: U1037.36(TX_D2) ; also on sheet 65
EMAC[0]_TXD3: U1037.35(TX_D3) ; also on sheet 65
EMAC[1]_RXC: U84.43(RX_CLK) ; also on sheet 25
EMAC[1]_RXCTL: R1140.1 R1141.1 U84.53(RX_DV/RX_CTRL) ; also on sheet 25
EMAC[1]_RXD0: R355.2 R359.1 U84.44(RX_D0) ; also on sheet 25
EMAC[1]_RXD1: U84.45(RX_D1) ; also on sheet 25
EMAC[1]_RXD2: R366.2 R373.1 U84.46(RX_D2) ; also on sheet 25
EMAC[1]_RXD3: U84.47(RX_D3) ; also on sheet 25
EMAC[1]_TXC: U84.40(GTX_CLK) ; also on sheet 25
EMAC[1]_TXCTL: U84.52(TX_EN/TX_CTRL) ; also on sheet 25
EMAC[1]_TXD0: U84.38(TX_D0) ; also on sheet 25
EMAC[1]_TXD1: U84.37(TX_D1) ; also on sheet 25
EMAC[1]_TXD2: U84.36(TX_D2) ; also on sheet 25
EMAC[1]_TXD3: U84.35(TX_D3) ; also on sheet 25
ENET_INT_P0: R1129.2 U1037.60(INT/PWDN) ; also on sheet 46
ENET_INT_P1: R357.2 U84.60(INT/PWDN) ; also on sheet 46
ENET_PORz: U10.1(B) U85.1(B) ; also on sheet 11
EVM_1V8: EXP_P2.55 EXP_P2.56 R273.2 R473.1 R1020.2 U1017.9(VIN-) ; also on sheet 29 37 40 44 45 46 59
EVM_3V3: C37.1 C43.1 C249.1 C263.1 C270.1 C282.1 C1003.1 C1076.1 C1078.1 C1079.1 C1081.1 C1082.1 C1084.1 C1090.1 EXP_P2.57 EXP_P2.58 EXP_P2.59 EXP_P2.60 R283.2 R355.1 R357.1 R362.1 R373.2 R435.2 R441.2 R447.2 R480.1 R1114.1 R1117.2 R1118.1 R1119.2 R1120.2 R1121.2 R1129.1 R1133.2 R1135.2 R1137.2 R1139.2 R1141.2 RU117.16(VCC) U10.5(VCC) U84.23(VDDIO) U84.41(VDDIO) U84.57(VDDIO) U85.5(VCC) U1001.34(VIO_IN) U1037.23(VDDIO) U1037.41(VDDIO) U1037.57(VDDIO) ; also on sheet 3 4 10 11 24 25 26 27 28 29 30 31 32 33 34 35 36 37 38 39 40 42 43 44 45 46 58 59 62 63 65 66 67 69 70
EVM_5V0: EXP_P2.65 EXP_P2.66 R138.2 U92.4(VBIAS) U138.4(VBIAS) ; also on sheet 25 30 31 36 37 38 40 41 45 58 63 68
EVM_12V: C45.1 C47.1 C49.1 C50.1 C51.1 C52.1 C62.2 C63.2 EXP_P2.49 EXP_P2.50 EXP_P2.51 EXP_P2.52 EXP_P2.53 EXP_P2.54 J7.1 Q1.5(D1) Q2.5(D1) R141.1 R142.1 R775.2 U23.38(VIN) ; also on sheet 3 36 58
EVM_DDR_VTT: C188.2 C192.2 C202.2 C658.2 R290.2 R293.1 TP64.1 U64.3(VO)
EVM_VDD_DDR: C187.2 C191.2 C201.2 C659.2 R292.2 R1014.2 U64.2(VLDOIN) U1001.45(SMPS5_FDBK) U1011.9(VIN-) ; also on sheet 20 21 22 23 59
EXP_ETH0_RSTn: U10.2(A) ; also on sheet 42
EXP_ETH1_RSTn: U85.2(A) ; also on sheet 42
GA1: R451.2 U23.6(GA1)
GA2: R457.2 U23.8(GA2)
GB1: R450.2 U23.33(GB1)
GB2: R456.2 U23.31(GB2)
GP2[27]: EXP_P2.108 ; also on sheet 4 24
GP5[0]: EXP_P2.34 ; also on sheet 2 59
GP5[1]: EXP_P2.36 ; also on sheet 2
GP5[17]: EXP_P2.32 ; also on sheet 64
GP5[22]: EXP_P1.33 ; also on sheet 65
GP5[25]: EXP_P1.35 ; also on sheet 65
GP5[29]: EXP_P1.34 ; also on sheet 65
GP5[30]: EXP_P1.36 ; also on sheet 65
GP5[31]: EXP_P1.38 ; also on sheet 65
GP6[17]: EXP_P1.15 ; also on sheet 2
GP6[20]: EXP_P3.13 ; also on sheet 2
GPIO6[10]: RU117.2(1B1) ; also on sheet 62
GPIO6[11]: RU117.5(2B1) ; also on sheet 62
I2C1_SCL: EXP_P2.30 U1001.35(I2C1_SCL_SCK) ; also on sheet 3 34 37 42 45 62 69
I2C1_SDA: EXP_P2.28 U1001.36(I2C1_SDA_SDI) ; also on sheet 3 34 37 42 45 62 69
I2C3_SCL: EXP_P1.1 ; also on sheet 59 67
I2C3_SDA: EXP_P1.3 ; also on sheet 59 67
I2C4_SCL: EXP_P1.11 ; also on sheet 2
I2C4_SDA: EXP_P1.12 ; also on sheet 2
I2C5_SCL: EXP_P3.22 ; also on sheet 39 40 42 66
I2C5_SDA: EXP_P3.21 ; also on sheet 39 40 42 66
J6_VDD_1V8: R1018.2 U1001.17(SMPS4_FDBK) U1015.9(VIN-) ; also on sheet 3 11 13 14 59
J6_VDD_DDR: R822.2 R1011.2 U138.1(VIN.1) U138.2(VIN.2) U1008.9(VIN-) ; also on sheet 59
J6_VDD_GPU: R1013.2 U1001.9(SMPS3_FDBK) U1010.9(VIN-) ; also on sheet 17 59
J6_VDD_MPU: R554.1 R1010.2 U1001.33(SMPS1_FDBK) U1007.9(VIN-) ; also on sheet 17 59
LDO1_OUT: C1020.2 U1001.23(LDO1_OUT) ; also on sheet 58
LDO2_OUT: C1021.2 TP1017.1(TP) U1001.21(LDO2_OUT) ; also on sheet 58
LDO3_OUT: C1022.2 U1001.6(LDO3_OUT) ; also on sheet 58
LDO4_OUT: C1023.2 U1001.7(LDO4_OUT) ; also on sheet 58
LDO5_OUT: C1024.2 U1001.4(LDO5_OUT) ; also on sheet 58
LDOVANA: C1004.1 U1001.43(LDOVANA_OUT)
LDOVRTC: C1005.1 R516.2 U1001.44(LDOVRTC_OUT)
MCA2_ACLKX: EXP_P2.29 ; also on sheet 66
MCA2_AFSX: EXP_P2.31 ; also on sheet 66
MCA2_AXR0: EXP_P2.37 ; also on sheet 66
MCA2_AXR1: EXP_P2.33 ; also on sheet 66
MCA2_AXR2: EXP_P2.39 ; also on sheet 66
MCA2_AXR3: EXP_P2.35 ; also on sheet 66
MCA2_AXR4: EXP_P2.23 ; also on sheet 66
MCA2_AXR5: EXP_P2.24 ; also on sheet 66
MCA2_AXR6: EXP_P2.22 ; also on sheet 66
MCA2_AXR7: EXP_P2.38 ; also on sheet 66
MCA4_AXR0: EXP_P1.18 ; also on sheet 2
MCA4_AXR1: EXP_P1.9 ; also on sheet 2
MCA5_ACLKX: EXP_P1.8 ; also on sheet 2
MCA5_AXR0: EXP_P1.6 ; also on sheet 2
MCA5_AXR1: EXP_P1.5 ; also on sheet 2
MCA5_FSX: EXP_P1.7 ; also on sheet 2
MCA6_ACLKX: EXP_P2.104 ; also on sheet 66
MCA6_AFSX: EXP_P2.102 ; also on sheet 66
MCA6_AHCLKX: EXP_P2.106 ; also on sheet 66
MCA6_AXR0: EXP_P2.103 ; also on sheet 66
MCA6_AXR1: EXP_P2.105 ; also on sheet 66
MDIO_MDCLK: U84.20(MDC) U1037.20(MDC) ; also on sheet 46 65
MDIO_MDIO: U84.21(MDIO) U1037.21(MDIO) ; also on sheet 46 65
MMC3_CLK: EXP_P3.25 ; also on sheet 61
MMC3_CMD: EXP_P3.26 ; also on sheet 61
MMC3_DAT0: EXP_P3.28 ; also on sheet 61
MMC3_DAT1: EXP_P3.30 ; also on sheet 61
MMC3_DAT2: EXP_P3.27 ; also on sheet 61
MMC3_DAT3: EXP_P3.29 ; also on sheet 61
MMC3_DAT4: EXP_P3.32 ; also on sheet 61
MMC3_DAT5: EXP_P3.34 ; also on sheet 61
MMC3_DAT6: RU117.3(1B2) ; also on sheet 61
MMC3_DAT7: RU117.6(2B2) RU117.11(3B1) ; also on sheet 61
MMC3_SEL: R1133.1 RU117.1(S) ; also on sheet 42
OLD_GPMC_nCS0: EXP_P1.16 R480.2
P0_CRS: R1134.1 R1135.1 U1037.56(CRS/GPIO)
P0_LED_ACT: R1125.2 U1037.63(LED_0)
P0_LED_LINK10_100: RJ4.3 U1037.61(LED_2)
P0_LED_LINK1000: R1126.2 U1037.62(LED_1)
P0_RBIAS: R1132.2 U1037.15(RBIAS)
P0_RX_D4: R1114.2 R1123.1 U1037.48(RX_D4/GPIO)
P0_RX_D5: R1116.2 R1119.1 U1037.49(RX_D5/GPIO)
P0_RX_D6: R1115.2 R1121.1 U1037.50(RX_D6/GPIO)
P0_RX_D7: R1113.1 R1120.1 U1037.51(RX_D7/GPIO)
P0_TRD[0]N: P5.10(T0-) U1037.3(TD_M_A)
P0_TRD[0]P: P5.9(T0+) U1037.2(TD_P_A)
P0_TRD[1]N: P5.8(T1-) U1037.6(TD_M_B)
P0_TRD[1]P: P5.7(T1+) U1037.5(TD_P_B)
P0_TRD[2]N: P5.6(T2-) U1037.11(TD_M_C)
P0_TRD[2]P: P5.5(T2+) U1037.10(TD_P_C)
P0_TRD[3]N: P5.4(T3-) U1037.14(TD_M_D)
P0_TRD[3]P: P5.3(T3+) U1037.13(TD_P_D)
P1_CRS: R1138.1 R1139.1 U84.56(CRS/GPIO)
P1_LED_ACT: R297.2 U84.63(LED_0)
P1_LED_LINK10_100: RJ3.3 U84.61(LED_2)
P1_LED_LINK1000: R296.2 U84.62(LED_1)
P1_RBIAS: R348.2 U84.15(RBIAS)
P1_RX_D4: R361.1 R362.2 U84.48(RX_D4/GPIO)
P1_RX_D5: R369.2 R441.1 U84.49(RX_D5/GPIO)
P1_RX_D6: R380.2 R447.1 U84.50(RX_D6/GPIO)
P1_RX_D7: R386.1 R435.1 U84.51(RX_D7/GPIO)
P1_TRD[0]N: P6.10(T0-) U84.3(TD_M_A)
P1_TRD[0]P: P6.9(T0+) U84.2(TD_P_A)
P1_TRD[1]N: P6.8(T1-) U84.6(TD_M_B)
P1_TRD[1]P: P6.7(T1+) U84.5(TD_P_B)
P1_TRD[2]N: P6.6(T2-) U84.11(TD_M_C)
P1_TRD[2]P: P6.5(T2+) U84.10(TD_P_C)
P1_TRD[3]N: P6.4(T3-) U84.14(TD_M_D)
P1_TRD[3]P: P6.3(T3+) U84.13(TD_P_D)
PB_ON: J4.2 R12.1 R13.1 SW9.3(B) SW9.4(BB) ; also on sheet 59
PCF8575_INT: R1099.1 ; also on sheet 25 42
PGD_3V3_5V0: R138.1 R140.1 R1037.1 U23.15(PGA) U23.24(PGB)
PHA: C300.1 L6.1 Q1.1(S1) Q1.2(S2) Q1.3(S3) Q3.5(D1) R126.2 U23.7(PHA)
PHB: C299.1 L7.1 Q2.1(S1) Q2.2(S2) Q2.3(S3) Q4.5(D1) R127.2 U23.32(PHB)
PHY_1V1: C247.1 C248.1 C260.1 C281.1 C283.1 C289.1 C1083.1 C1085.1 C1086.1 C1089.1 C1091.1 C1095.1 U84.8(VDD1P1) U84.29(VDD1P1) U84.42(VDD1P1) U84.58(VDD1P1) U1037.8(VDD1P1) U1037.29(VDD1P1) U1037.42(VDD1P1) U1037.58(VDD1P1) ; also on sheet 46
PHY_2V5: C237.1 C240.1 C246.1 C284.1 C1088.1 C1092.1 C1093.1 C1094.1 U84.4(VDDA2P5) U84.12(VDDA2P5) U1037.4(VDDA2P5) U1037.12(VDDA2P5) ; also on sheet 46
PM1_SCL: J1001.1 R1005.1 U1005.4(IO3) U1006.5(SCL) U1007.5(SCL) U1008.5(SCL) U1009.5(SCL) U1010.5(SCL) U1011.2(A0) U1011.5(SCL) U1012.5(SCL) U1013.2(A0) U1013.5(SCL) U1014.2(A0) U1014.5(SCL) U1015.5(SCL) U1016.5(SCL) U1017.5(SCL) ; also on sheet 59
PM1_SDA: J1001.2 R1006.1 U1005.5(IO4) U1006.4(SDA) U1007.4(SDA) U1008.1(A1) U1008.2(A0) U1008.4(SDA) U1009.4(SDA) U1010.2(A0) U1010.4(SDA) U1011.1(A1) U1011.4(SDA) U1012.2(A0) U1012.4(SDA) U1013.4(SDA) U1014.4(SDA) U1015.1(A1) U1015.4(SDA) U1016.4(SDA) U1017.1(A1) U1017.4(SDA) ; also on sheet 59
PM2_SCL: J1001.5 R1007.2 U1005.3(IO2) ; also on sheet 58 59
PM2_SDA: J1001.4 R1008.2 U1005.1(IO1) ; also on sheet 58 59
PM_PORn: R9357.1 ; also on sheet 59
PM_RESETn: R9358.1 ; also on sheet 59
PMIC_OFF: R797.1 ; also on sheet 11 41
PMIC_REGEN_3V3: R473.2 U92.3(ON) U1001.12(GPIO_0)
PMIC_REGEN_DDR: R273.1 U138.3(ON) U1001.15(GPIO_5)
PMIC_RESET_OUT: U1001.25(RESET_OUT) ; also on sheet 11
RSTOUTn: U1001.13(GPIO_1) ; also on sheet 3 11 26 28 29 34 35 40 59
SMPS1: C1013.2 L1001.1 R1010.1 U1007.8(VBUS) U1007.10(VIN+) ; also on sheet 59
SMPS1_IN: C1008.2 R1009.2 U1001.32(SMPS1_IN) U1006.9(VIN-)
SMPS2: C1014.2 L1002.1 R1016.1 U1013.8(VBUS) U1013.10(VIN+) ; also on sheet 59
SMPS2_IN: C1009.2 R1012.2 U1001.29(SMPS2_IN) U1009.9(VIN-)
SMPS3: C1015.2 L1003.1 R1013.1 U1010.8(VBUS) U1010.10(VIN+) ; also on sheet 59
SMPS3_IN: C1010.2 R1015.2 U1001.10(SMPS3_IN) U1012.9(VIN-)
SMPS4: C1016.2 L1004.1 R1018.1 R1020.1 U1015.8(VBUS) U1015.10(VIN+) U1017.8(VBUS) U1017.10(VIN+) ; also on sheet 59
SMPS4_IN: C1011.2 R1017.2 U1001.18(SMPS4_IN) U1014.9(VIN-)
SMPS5: C1017.2 L1005.1 R1011.1 R1014.1 U1008.8(VBUS) U1008.10(VIN+) U1011.8(VBUS) U1011.10(VIN+) ; also on sheet 59
SMPS5_IN: C1012.2 R1019.2 U1001.46(SMPS5_IN) U1016.9(VIN-)
SPI[1]_CS[0]n: EXP_P3.36 ; also on sheet 62
SPI[1]_CS[1]n: EXP_P3.39 R808.2 ; also on sheet 62
SPI[1]_MISO: EXP_P3.37 ; also on sheet 62
SPI[1]_MOSI: EXP_P3.38 ; also on sheet 62
SPI[1]_SCLK: EXP_P3.35 ; also on sheet 62
SPI[2]_CS[0]n: EXP_P3.2 ; also on sheet 67
SPI[2]_MISO: EXP_P3.3 ; also on sheet 67
SPI[2]_MOSI: EXP_P3.4 ; also on sheet 67
SPI[2]_SCLK: EXP_P3.1 ; also on sheet 67
SW_VSYS_3V3: C319.1 U92.7(VOUT.2) U92.8(VOUT.1) ; also on sheet 58 59
TPS43351_GC2: TP831.1 U23.4(GC2)
VIN2B_HSYNC/MMC3_D6: EXP_P3.31 RU117.4(1A)
VIN2B_VSYNC/MMC3_D7: EXP_P3.33 RU117.7(2A)
VSYS_3V3: C71.1 C74.1 C174.2 C302.2 C441.1 C499.1 C683.1 C689.1 C690.1 C1001.1 C1019.2 C1026.2 C1027.2 C1028.2 C1029.2 C1030.2 C1031.2 C1032.2 C1033.2 C1034.2 C1035.2 C1036.2 C1037.2 C1038.2 R134.1 R140.2 R143.2 R282.2 R583.1 R596.2 R616.1 R623.2 R827.2 R1005.2 R1006.2 R1007.1 R1008.1 R1009.1 R1012.1 R1015.1 R1017.1 R1019.1 R1077.2 U23.11(SA2) U64.10(VIN) U92.1(VIN.1) U92.2(VIN.2) U102.6(VDD) U107.6(VDD) U1001.3(LDO5_IN) U1001.5(LDO3_IN) U1001.37(VCC_SENSE) U1006.6(VS) U1006.8(VBUS) U1006.10(VIN+) U1007.1(A1) U1007.2(A0) U1007.6(VS) U1008.6(VS) U1009.2(A0) U1009.6(VS) U1009.8(VBUS) U1009.10(VIN+) U1010.1(A1) U1010.6(VS) U1011.6(VS) U1012.6(VS) U1012.8(VBUS) U1012.10(VIN+) U1013.1(A1) U1013.6(VS) U1014.6(VS) U1014.8(VBUS) U1014.10(VIN+) U1015.6(VS) U1016.1(A1) U1016.6(VS) U1016.8(VBUS) U1016.10(VIN+) U1017.2(A0) U1017.6(VS) ; also on sheet 11 23 36 46 58
VSYS_5V0: C72.1 C77.1 C301.2 C684.1 C1025.2 R135.1 R147.2 R1076.2 U23.28(SB2) U1001.8(LDO4_IN) ; also on sheet 46 58
VSYS_12V0: Q5.5(D1) U8.8(CATHODE) ; also on sheet 58
VTT: R293.2 R826.1 TP65.1 ; also on sheet 23
WAKEUP3: U1001.26(INT) ; also on sheet 11
N16751051: L1001.2 U1001.31(SPMS1_SW)
N16751055: L1002.2 U1001.30(SPMS2_SW)
N16751059: L1003.2 U1001.11(SMPS3_SW)
N16751063: L1004.2 U1001.19(SPMS4_SW)
N16751067: L1005.2 U1001.47(SMPS5_SW)
N16752940: C1007.2 U1001.40(VBG)
N16754645: SW7.3(B) SW7.4(BB) U1001.24(PWRON)
N16754673: TP1009.1(TP) U1001.2(GPIO)
N16754677: TP1010.1(TP) U1001.14(GPIO_3)
N16754681: TP1011.1(TP) U1001.1(GPIO_4)
N16754697: TP1015.1(TP) U1001.38(ADCIN1)
N16754701: TP1016.1(TP) U1001.39(ADCIN2)
N16758786: C1018.2 R1076.1 R1077.1 U1001.22(LDO12_IN)
N17043197: C707.1 D1.1(CATHODE) F1.1 Q5.1(S1) Q5.2(S2) Q5.3(S3) U8.4(ANODE)
N17182110: R13.2 R141.2 U23.16(ENA)
N17182418: R12.2 R142.2 U23.17(ENB)
N17213676: R463.2 U23.22(RT)
N17213686: C60.2 R126.1
N17213736: C61.2 R127.1
N17213790: C299.2 U23.34(CBB)
N17213830: C78.2 R145.2 R146.1 U23.27(FBB)
N17213836: C303.2 C304.2 U23.26(COMPB)
N17213838: C301.1 L7.2 R135.2 U23.29(SB1)
N17213987: C295.2 R454.2 U23.35(VREG)
N17214057: Q2.4(G) R450.1
N17214061: R146.2 R147.1
N17214151: C300.2 U23.5(CBA)
N17214195: C76.2 R144.1 R472.2 U23.12(FBA)
N17214201: C307.2 C309.2 U23.13(COMPA)
N17214229: C302.1 L6.2 R134.2 U23.10(SA1)
N17214255: R454.1 R455.2 U23.20(SYNC)
N17214311: C305.1 U23.14(SSA)
N17214457: R453.1 U23.1(VBAT)
N17214562: C314.1 U23.21(DLYAB)
N17214601: Q1.4(G) R451.1
N17214615: C306.1 U23.25(SSB)
N17214651: R143.1 R144.2
N17298856: EXP_P2.86 TP12.1
N18013683: EXP_P3.23 TP16.1
N19793183: DS5.2(ANODE) R775.1
N20246725: EXP_P2.107 TP8.1
N20787900: EXP_P2.100 TP14.1
N20789995: EXP_P2.99 TP7.1
N20790716: EXP_P2.101 TP10.1
N20829145: EXP_P3.10 TP29.1
N20830357: EXP_P3.16 TP21.1
N20849521: EXP_P3.9 TP28.1
N20849522: EXP_P3.15 TP20.1
N21735033: Q6.1(G) R283.1 R803.2 R808.1 U64.7(EN)
N21735270: C186.2 R291.2 R292.1 U64.1(REFIN)
N21735316: R282.1 U64.9(PGOOD)
N21735318: C179.2 R290.1 U64.5(VOSNS)
N22085306: R810.1 SW9.1(A) SW9.2(AA)
N22172983: R483.2 R516.1 U1001.16(BOOT)
N22175775: C702.1 U138.6(CT)
N22200716: R554.2 R555.2 U102.5(SENSE1) U107.5(SENSE1)
N22200753: C1097.1 R583.2 R1037.2 R9357.2 SW4.3(B) SW4.4(BB) U102.3(~{MR})
N23734399: TP1018.1(TP) U1001.48(SYNCCLKOUT)
N24498670: Q7.D R826.2
N24498704: Q6.3(D) Q7.G R827.1
N24704147: C421.1 U102.4(CT)
N24704160: C476.1 U107.4(CT)
N24704170: C1098.1 R616.2 R9358.2 SW6.3(B) SW6.4(BB) U107.3(~{MR})
N25236437: R589.1 R797.2 U1001.27(GPIO_6)
N25238065: D1.2(ANODE) D2.2(ANODE)
N25238102: C706.2 U8.7(VCAPH)
N25238134: Q5.4(G) U8.2(GT_PULL_DWN) U8.6(GATE_DRV)
N25238144: C706.1 U8.1(VCAPL)
N25402422: C250.1 R387.1 U84.18(XO) Y7.2
N25402435: C258.1 R387.2 U84.19(XI) Y7.1
N25404148: R399.2 U84.24(JTAG_TRSTN)
N25404204: U84.59(RESETn) U85.4(Y)
N25471405: TP1023.1(TP) U84.22(CLK_OUT)
N25544146: P6.D2(LED1-KA) RJ3.2
N25544167: C224.1 P6.2(VCC)
N25544187: P6.D3(LED2-AK) R297.1
N25544310: P6.D1(LED1-AK) R296.1
N25730366: C1080.1 R1128.2 U1037.19(XI) Y10.1
N25730376: U10.4(Y) U1037.59(RESETn)
N25730417: C1087.1 R1128.1 U1037.18(XO) Y10.2
N25730756: P5.D2(LED1-KA) RJ4.2
N25730777: C1077.1 P5.2(VCC)
N25730797: P5.D3(LED2-AK) R1125.1
N25730865: P5.D1(LED1-AK) R1126.1
N25730955: R1127.2 U1037.24(JTAG_TRSTN)
N25731355: TP1024.1(TP) U1037.22(CLK_OUT)
N26353936: C303.1 R461.2
N26353937: C307.1 R464.2
N39995776: EXP_P3.17 TP18.1
N41867582: EXP_P3.11 TP25.1
N42741901: EXP_P2.119 TP9.1
N42741903: EXP_P2.117 TP11.1
N42747561: EXP_P2.118 TP13.1
N42747573: EXP_P2.120 TP15.1
N42946869: EXP_P3.7 TP33.1
N42946871: EXP_P3.5 TP35.1
N43009183: EXP_P3.6 TP36.1
N43033719: EXP_P3.8 TP34.1
N43059537: EXP_P3.18 TP19.1
N43079890: EXP_P3.12 TP26.1
N43079892: EXP_P3.14 TP66.1
N43162645: EXP_P3.24 TP17.1
N45361223: Q3.4(G) R457.1
N45364158: Q4.4(G) R456.1
N46501256: C318.1 U92.6(CT)

Not connected (* = marked no-connect by the designer): EXP_P1 13* 14*; EXP_P2 75; EXP_P3 40; RU117 10(3B2) 12(4A) 13(4B2) 14(4B1); U8 3(NC3)* 5(NC5)*; U23 2(NC.2) 3(NC.3) 18(NC.18) 36(NC.36) 37(EXTSUP); U84 1(RSV1)* 7(RSV7)* 9(RSV9)* 16(RSV16)* 17(VDDA1P8A)* 25(JTAG_CLK)* 26(JTAG_TDO)* 27(JTAG_TMS)* 28(JTAG_TDI)* 30(TX_CLK)* 31(TX_D7)* 32(TX_D6)* 33(TX_D5)* 34(TX_D4)* 39(TX_ER)* 54(RX_ER/GPIO)* 55(COL/GPIO)* 64(VDDA1P8B)*; U1006 3(ALERT/NC.3); U1007 3(ALERT/NC.3); U1008 3(ALERT/NC.3); U1009 3(ALERT/NC.3); U1010 3(ALERT/NC.3); U1011 3(ALERT/NC.3); U1012 3(ALERT/NC.3); U1013 3(ALERT/NC.3); U1014 3(ALERT/NC.3); U1015 3(ALERT/NC.3); U1016 3(ALERT/NC.3); U1017 3(ALERT/NC.3); U1037 1(RSV1)* 7(RSV7)* 9(RSV9)* 16(RSV16)* 17(VDDA1P8A)* 25(JTAG_CLK)* 26(JTAG_TDO)* 27(JTAG_TMS)* 28(JTAG_TDI)* 30(TX_CLK)* 31(TX_D7)* 32(TX_D6)* 33(TX_D5)* 34(TX_D4)* 39(TX_ER)* 54(RX_ER/GPIO)* 55(COL/GPIO)* 64(VDDA1P8B)*; ZJ1 1; ZJ2 1*; ZJ3 1*; ZJ4 1*

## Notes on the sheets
sheet 47
- AUTONEG DISABLE
- PHY_ADDR1/0
- PHY_ADDR3/2
- SPEED_SEL1/PHY_ADDR4
- MDI/X/FD/HD
- RGMII DISABLE/AMDIX DISABLE
- SPEED OPT/CLK OUT DISABLE
- FAST LINK DETECT
- PHY ADDR 2, TO MATCH VAYU EVM.
  BEWARE SOC PD  IMPACTS PU/PD RESISTOR SELECTION FOR PHY ADDR 3:0.
  DISABLING SOC PD WILL ALSO CAUSE DIFFERENT
  SENSE RESULTS WITH COLD BOOT AND SW APPLIED RESET.
  RECOMMEND THAT SOC PD NOT BE DISABLED.
sheet 48
- AUTONEG DISABLE
- PHY_ADDR1/0
- PHY_ADDR3/2
- SPEED_SEL1/PHY_ADDR4
- MDI/X/FD/HD
- RGMII DISABLE/AMDIX DISABLE
- SPEED OPT/CLK OUT DISABLE
- FAST LINK DETECT
- PHY ADDR 3, TO MATCH VAYU EVM.
  BEWARE SOC PD  IMPACTS PU/PD RESISTOR SELECTION FOR PHY ADDR 3:0.
  DISABLING SOC PD WILL ALSO CAUSE DIFFERENT
  SENSE RESULTS WITH COLD BOOT AND SW APPLIED RESET.
  RECOMMEND THAT SOC PD NOT BE DISABLED.
sheet 49
- MMC3_D7/VIN2B_CLK1/AB5/P1.P17
- JAMR2 BOARD MOUNTING HOLES
sheet 50
- DEMUX_FPD_A
- DEMUX_FPD_B
- DEMUX_FPD_C
- MUX1_SEL0
- MUX1_SEL1
- MUX2_SEL0
- MUX2_SEL1
- 113
sheet 51
- GPIO6_10/VIN2B_HSYNC/AC5/P3.P31
- GPIO6_11/VIN2B_VSYNC/AB4/P3.P33
- APP_BD_PRESENT_DETECTn
- S0=L A->B1, S0=H A->B2
- MMC3_D7/VIN2B_CLK1/AB5/P1.P17
- SELECTION GROUPED WITH RU93/RU115 VIN2 vs ENET/MMC3.
sheet 53
- VBATT
  12v
- PMON INSERTED HERE
- Input
- ER13
- OPTIONAL FAN CONNECTOR
- DISTRIBUTE ON BOARD, ONE GND TESTPOINT BY MLB CONNECTOR
sheet 54
- POSSIBLE HIGHER VOLTAGE RANGE ON C62, CHANGE FOOTPRINT TO 1210.
- ER20
- 10TPB100ML
- 10 Volts
- Less than ESR 35m-ohm
- POSSIBLE HIGHER VOLTAGE RANGE ON C63
- Fsw = 400KHZ
- 10 Volts
- Less than ESR 35m-ohm
- GRM32ER61A476KE20L (1210-10V)
  T525D476M016ATE035 (7343-16V)
- 100uF total
sheet 55
- (SMPS4)
- ER14
- 1.2 volt input
- 1.2 volt input
- (SMPS4)
- ER14
- R283 INSTALLED FOR NORMAL USE.
   R803 INSTALLED FOR FAST
  SHUTDOWN/RESUME FEATURE.
- AO3404A -RDSON ~ 35mOHM
- TURN ON ~1.2v
sheet 56
- VAYU EVM MAIN SUPPLY CONNECTIONS
- CHANGE PS_EVM_5V0 TO VSYS_5V0 AT MAIN REG
- CHANGE PS_EVM_3V3 TO VSYS_3V3 AT MAIN REG
- VSYS_3V3 TO VIO
- MAP EVM_5V0 TO PS_EVM_5V0 AT CURRENT MON.
- MAP EVM_3V3 TO PS_EVM_3V3_SW AT CURRENT MON.
- MAKE CONNECTIONS AT VAYU
- (VRTC)
- (VSYS)
- (VIO)
- (VIO)
- (VIO)
- (VIO)
- POSSIBLE ISSUE USING VRTC
  DOMAIN I/O. DO WE NEED TO
  ISOLATE.
- OPEN-DRAIN
- (VRTC)
- (VRTC)
- (VIO)
- (VRTC)
- (VIO)
- (VRTC)
- (VRTC)
- ER12
- SB TO I2C CONTROLLER
  SD PART# 703782-0001
sheet 57
- 100-0000 (0x40)
- 100-0101 (0x45)
- 100-1010 (0x4A)
- 100-0001 (0x41)
- 100-0110 (0x46)
- 100-1011 (0x4B)
- 100-0010 (0x42)
- 100-0111 (0x47)
- 100-0011 (0x43)
- 100-1000 (0x48)
- 100-0100 (0x44)
- 100-1001 (0x49)
